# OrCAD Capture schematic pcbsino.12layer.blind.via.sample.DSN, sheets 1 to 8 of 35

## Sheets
1 Pg08: DDR3 Memory 1: size C; title: TITLE; rev: C; company: Texas Instruments; note: Proj PROC053C-003 OPN# TMDSIDK572; note: Catalog Processors BU; note: Final
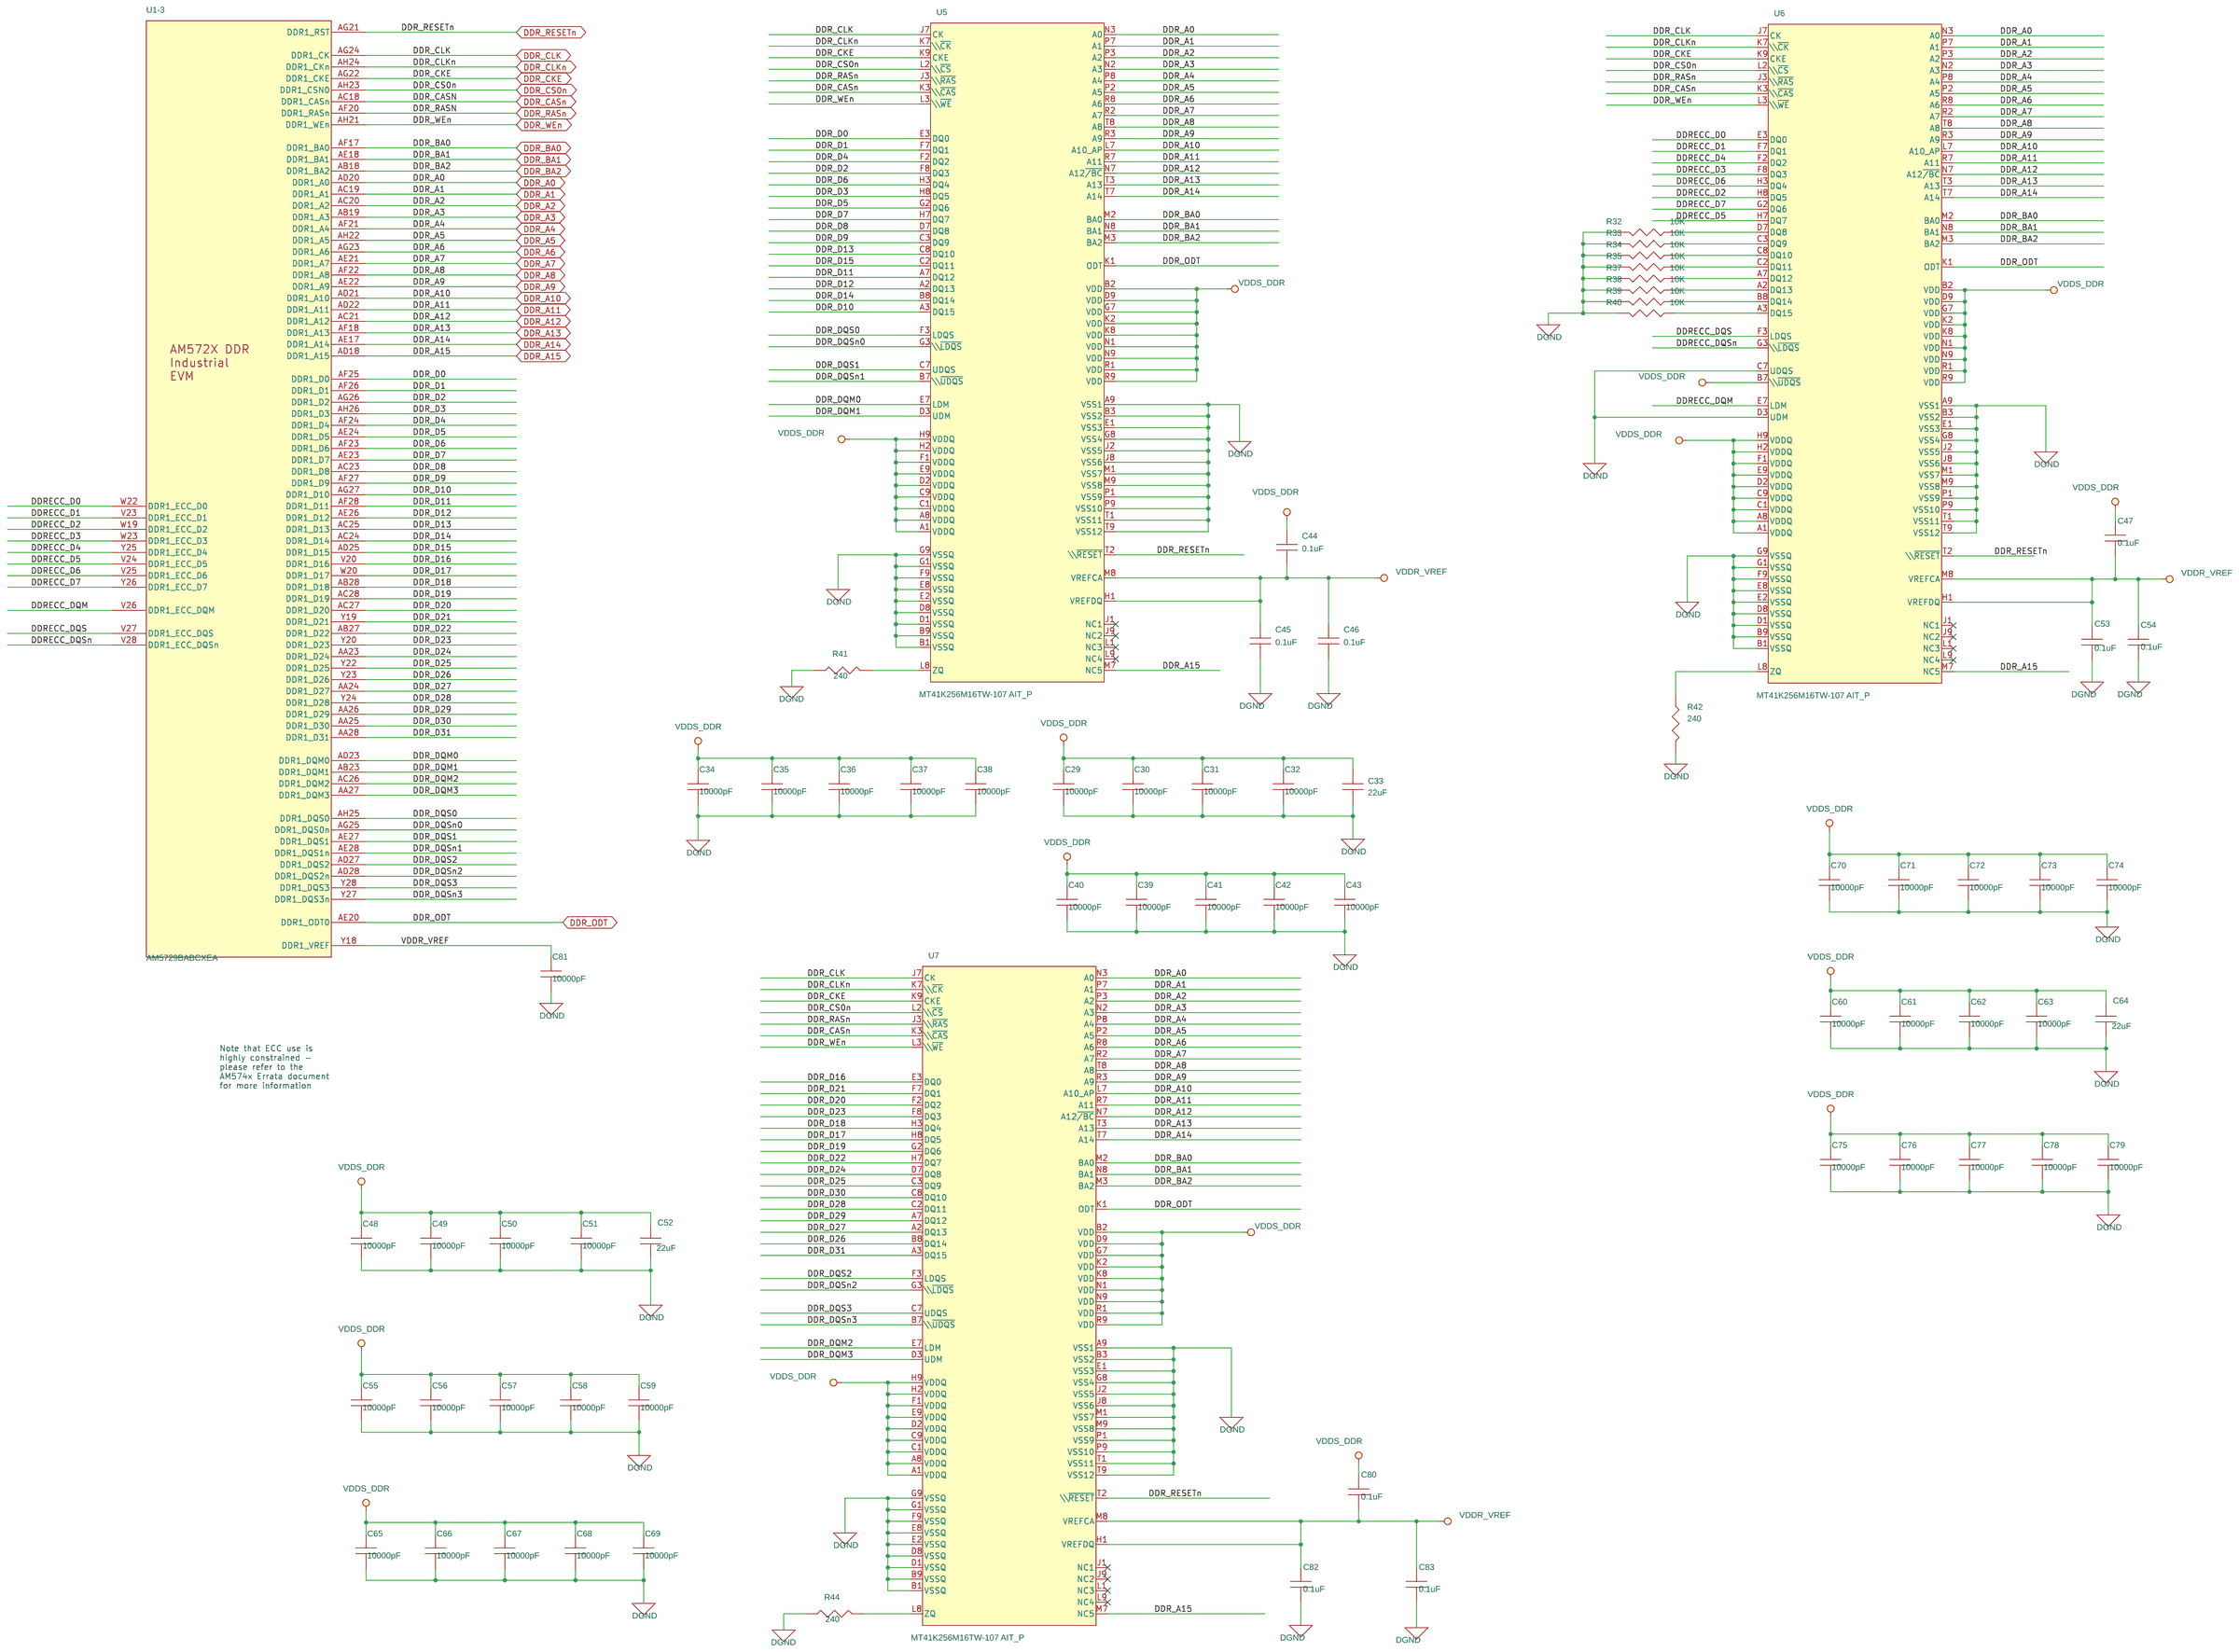
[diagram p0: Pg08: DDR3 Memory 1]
2 Pg24: USB JTAG: size C
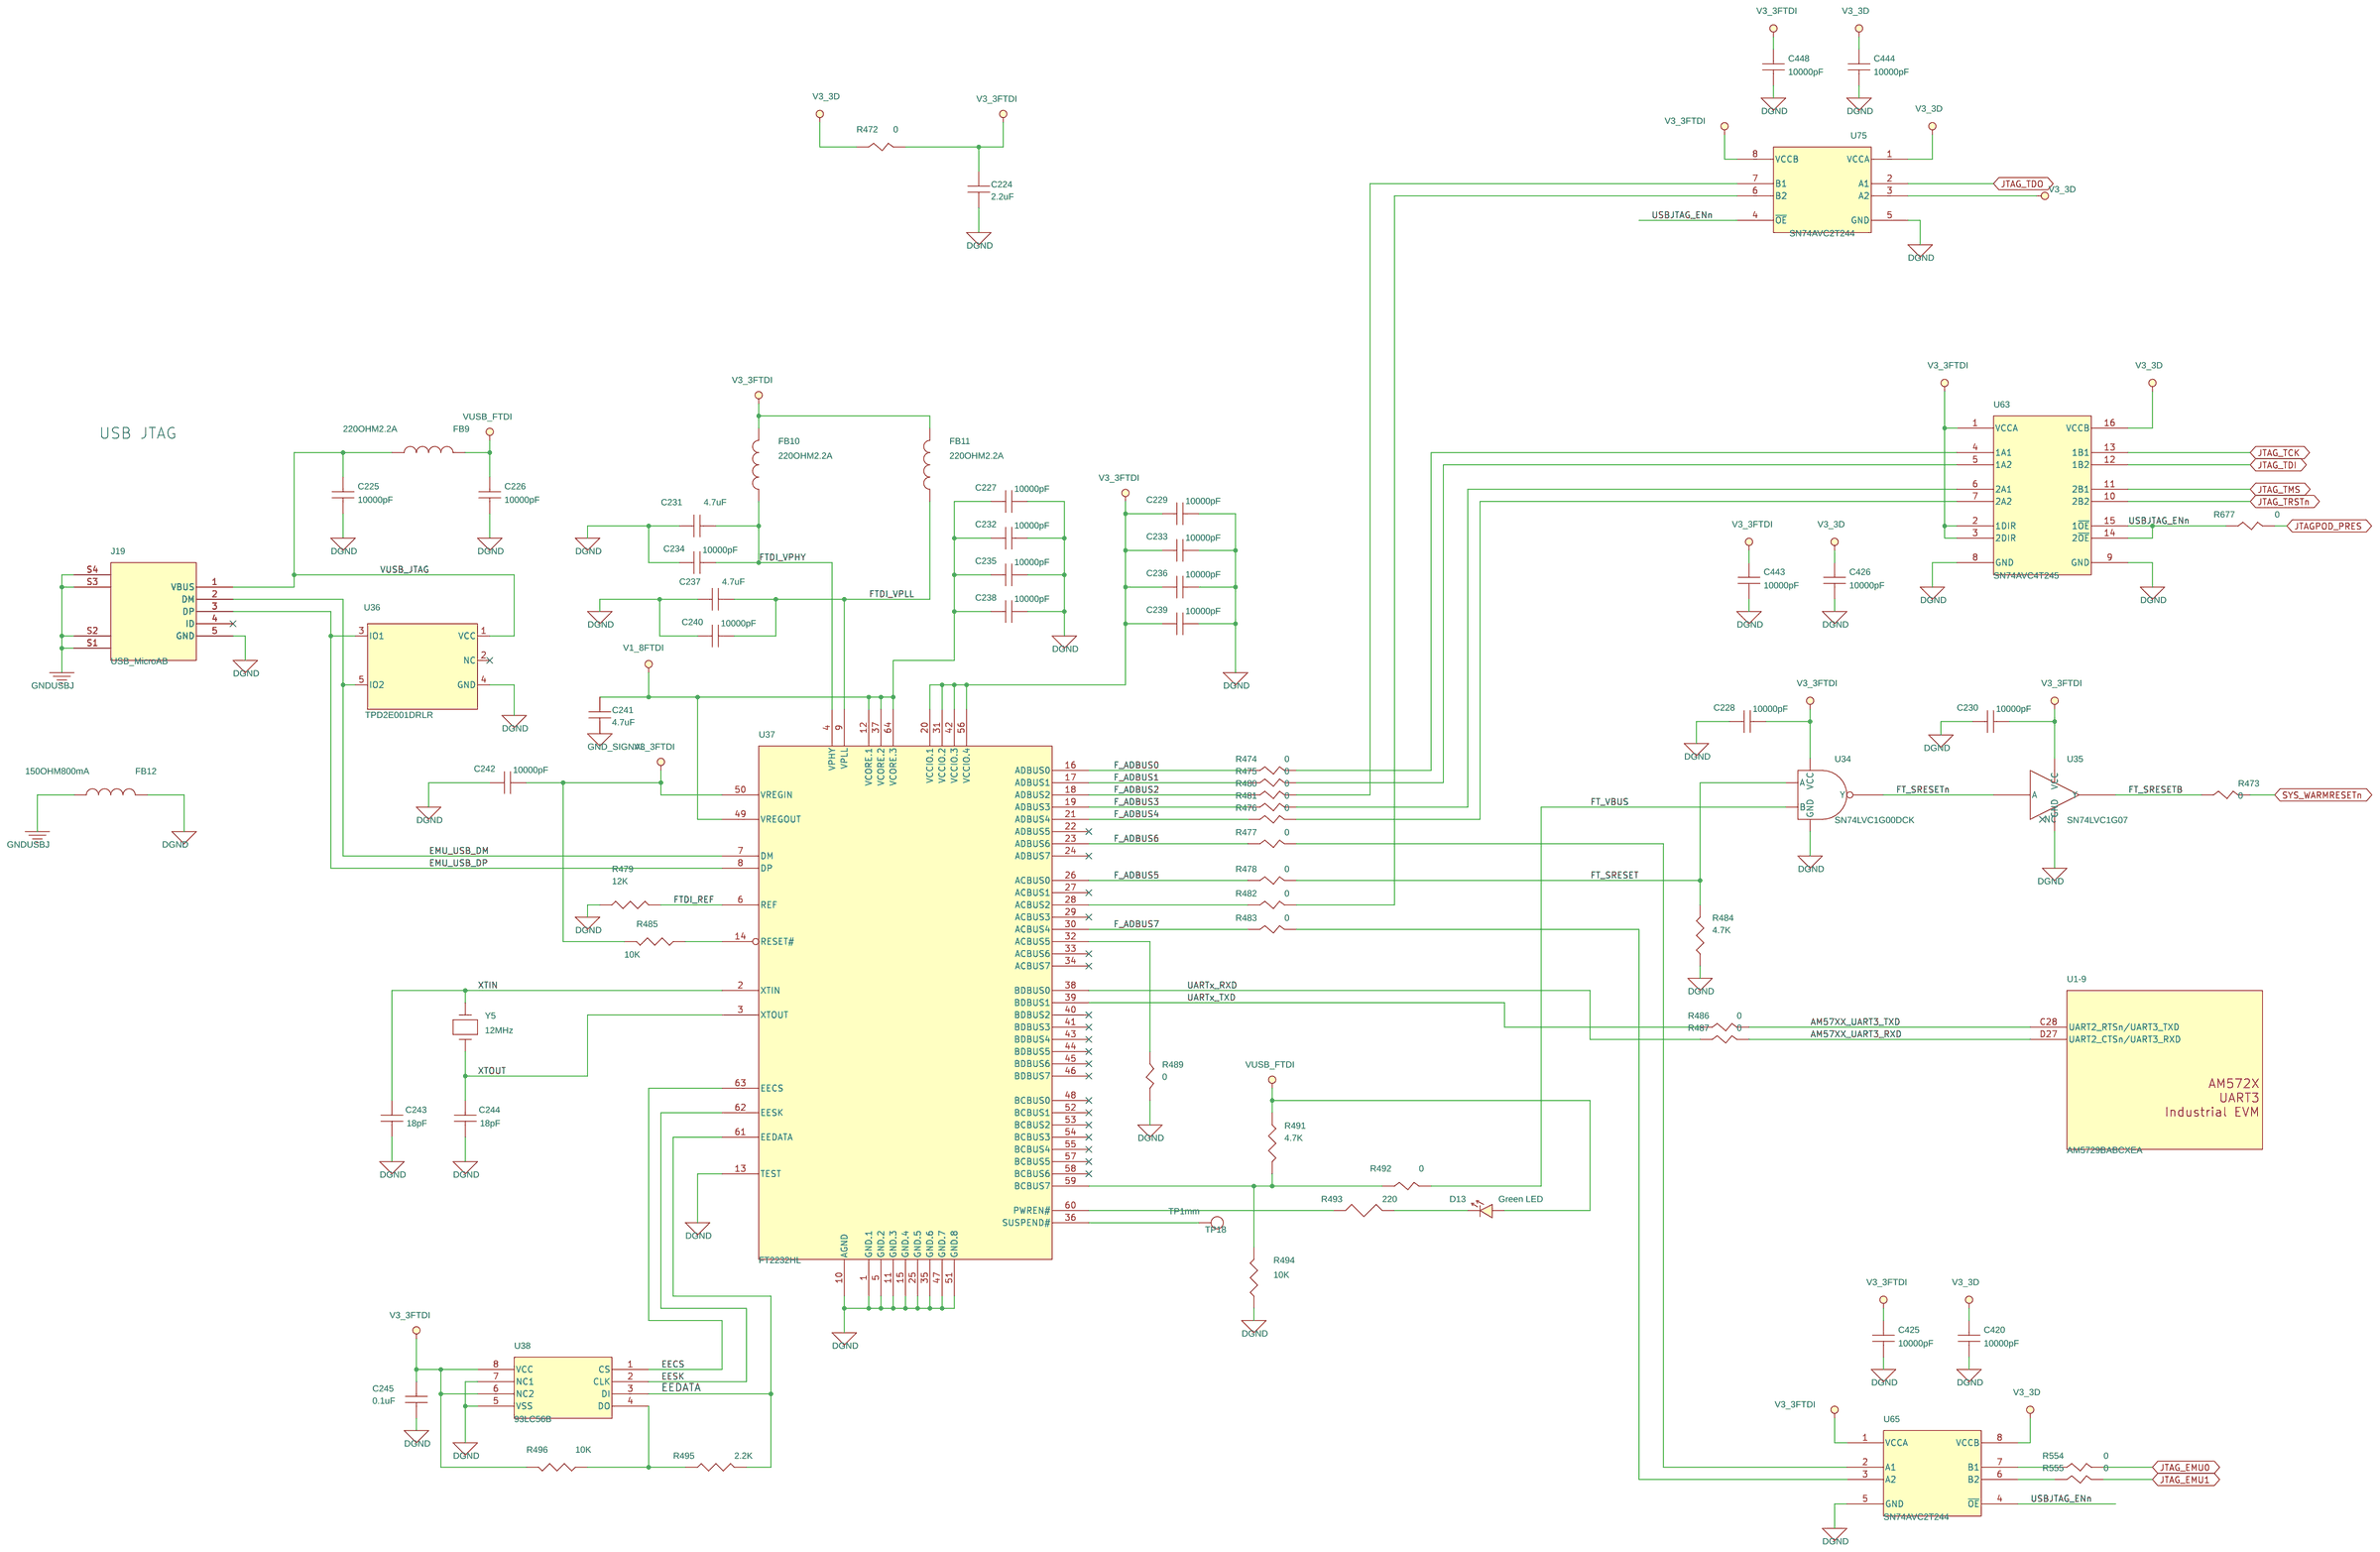
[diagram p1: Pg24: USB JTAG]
3 Pg30: RS-485: size C
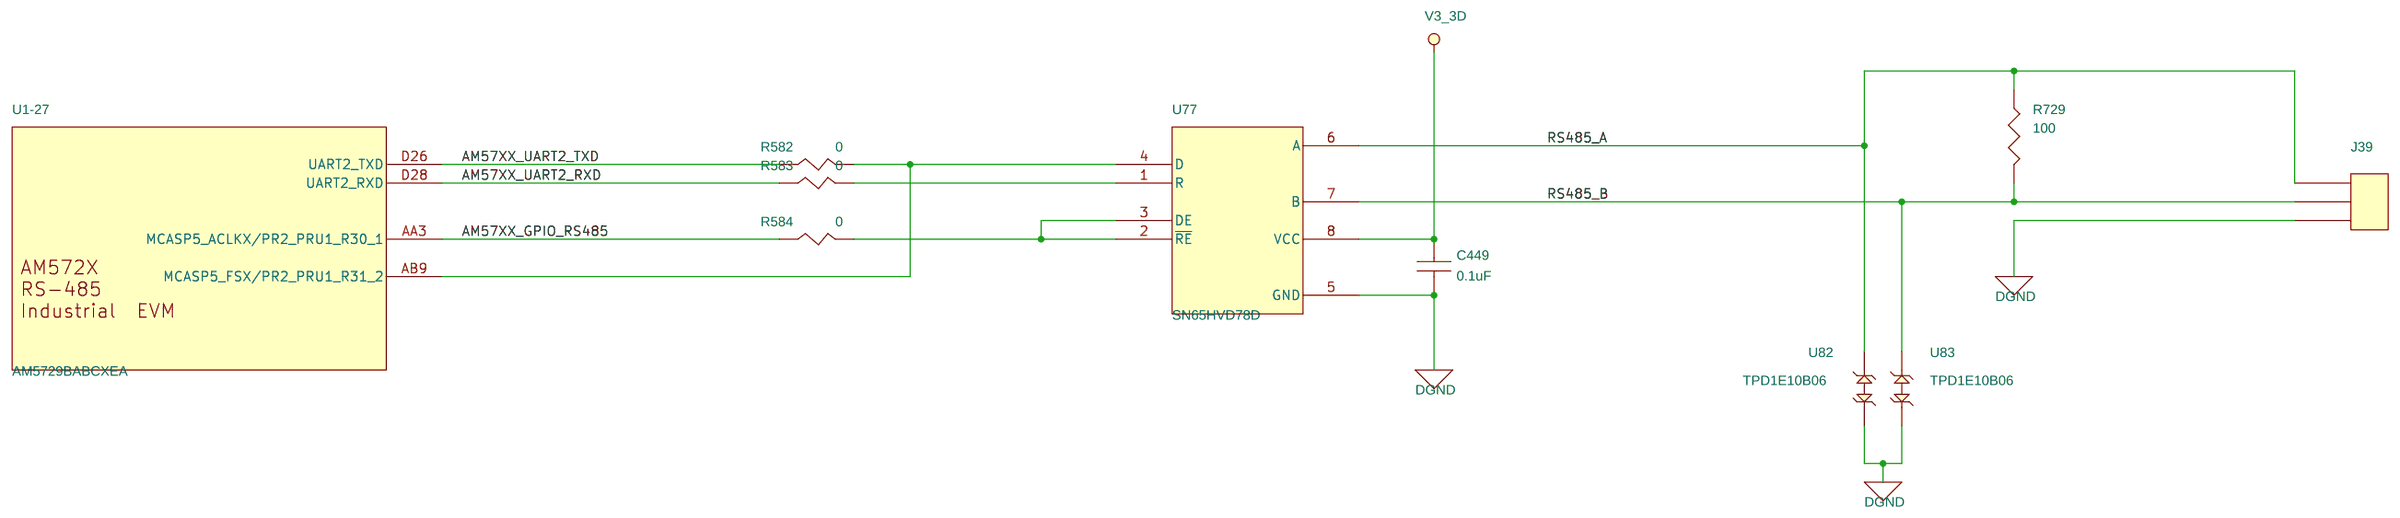
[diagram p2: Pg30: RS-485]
4 Pg22: HDMI: size C
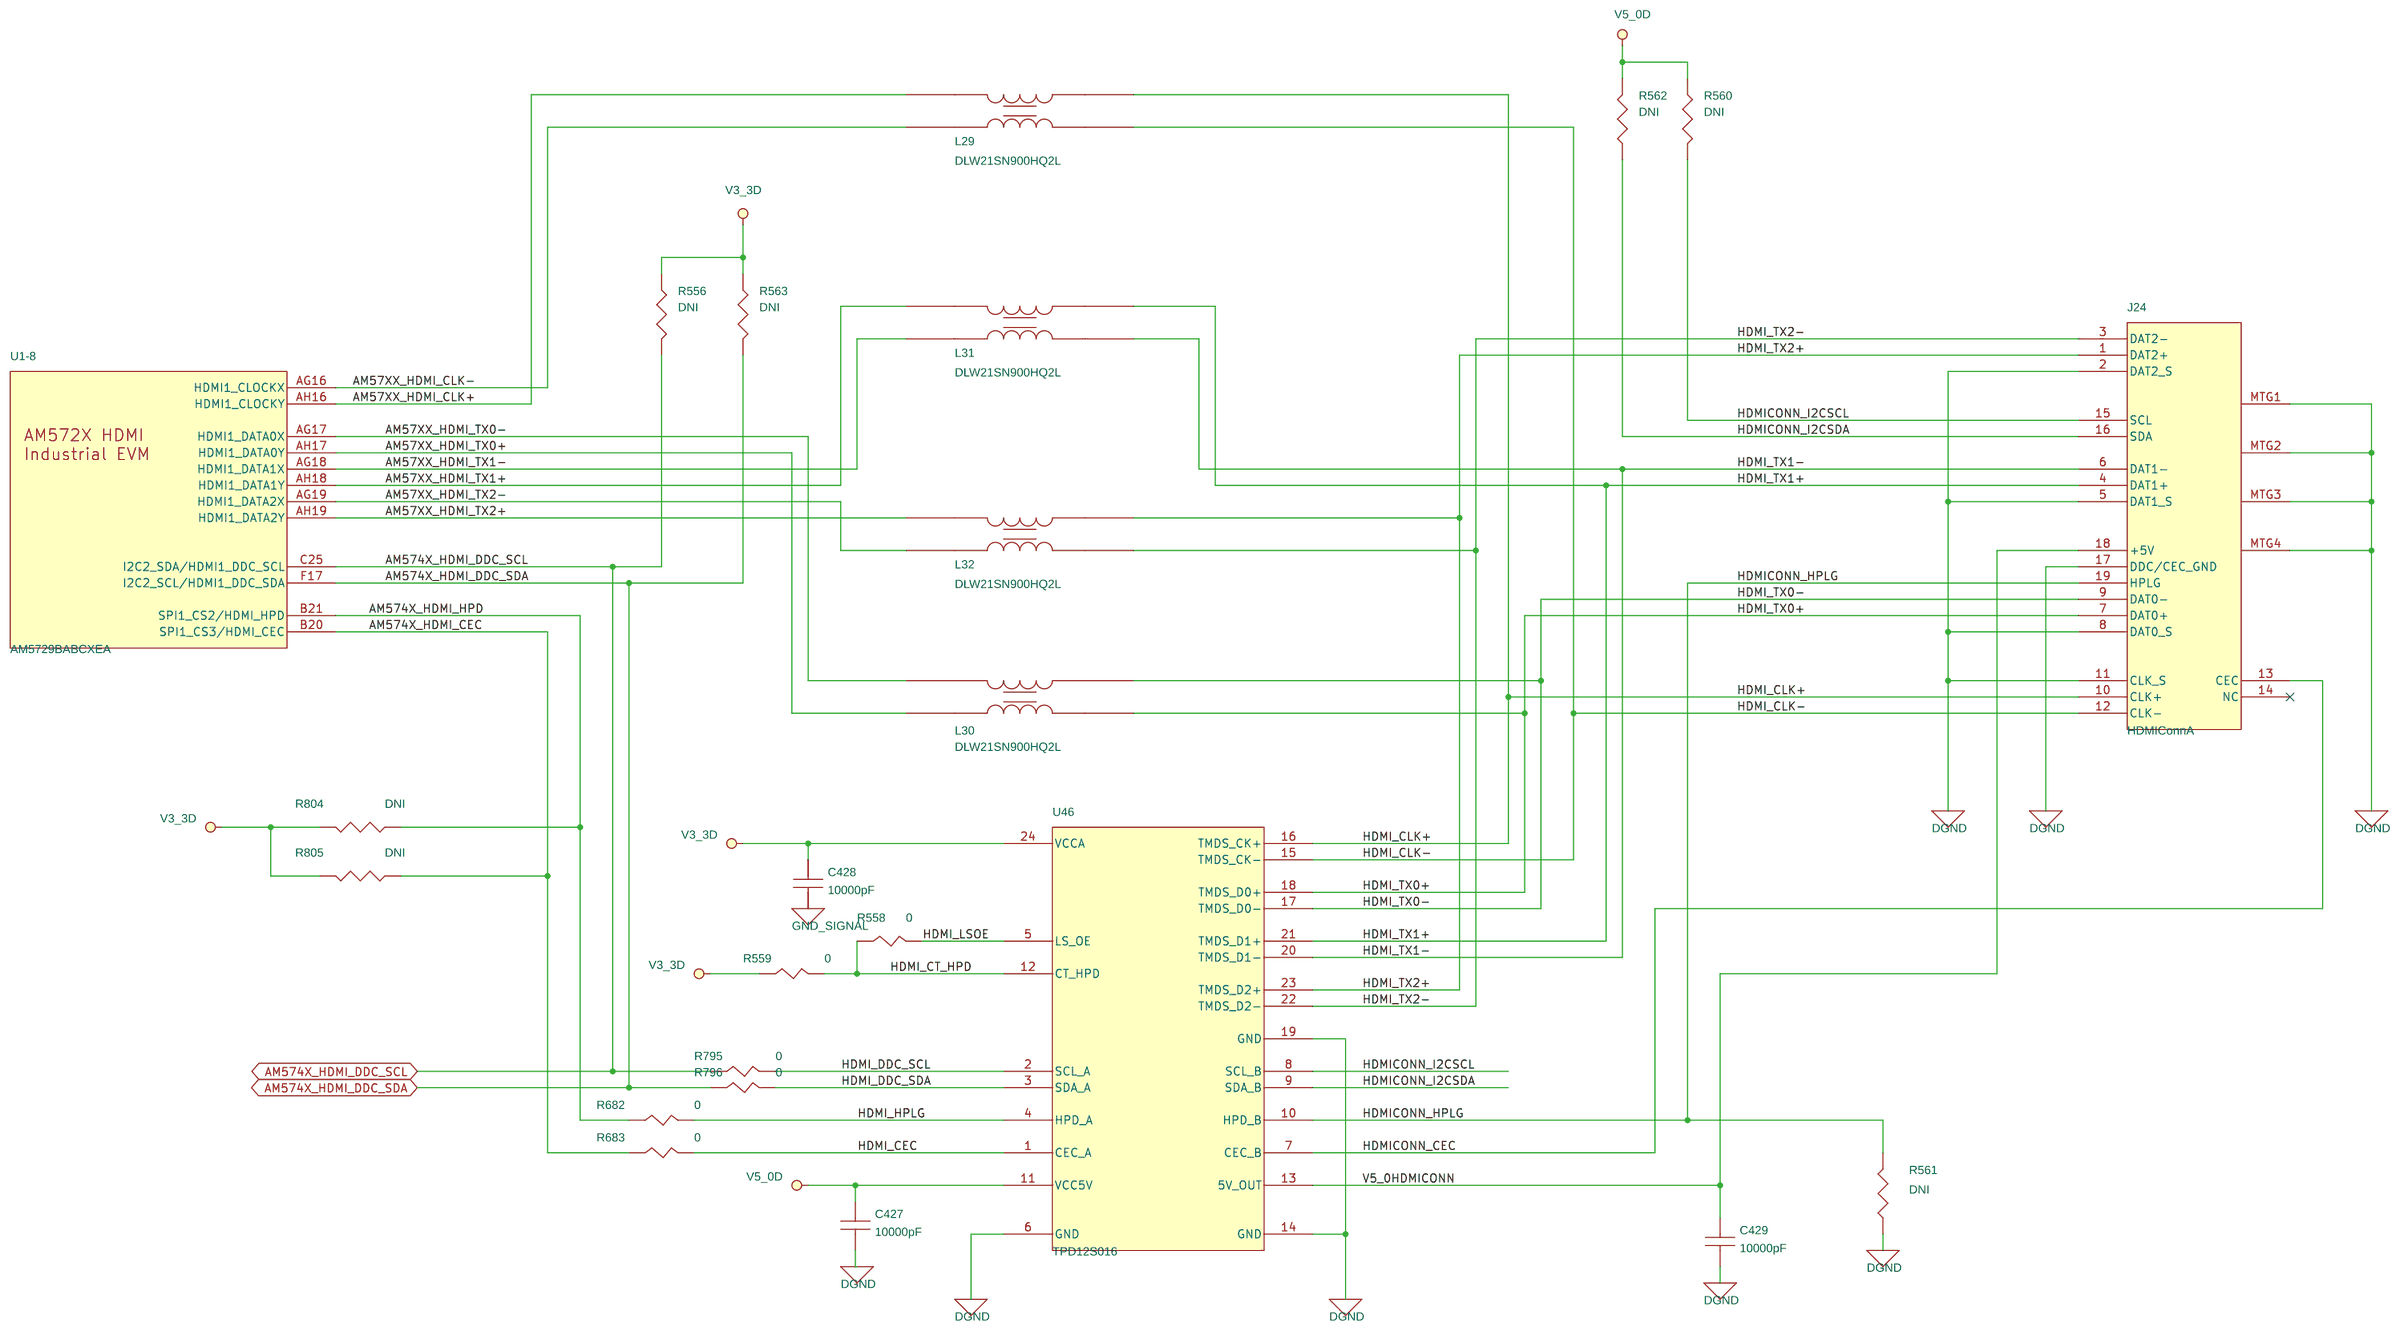
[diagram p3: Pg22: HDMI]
5 Pg21: LCD: size C
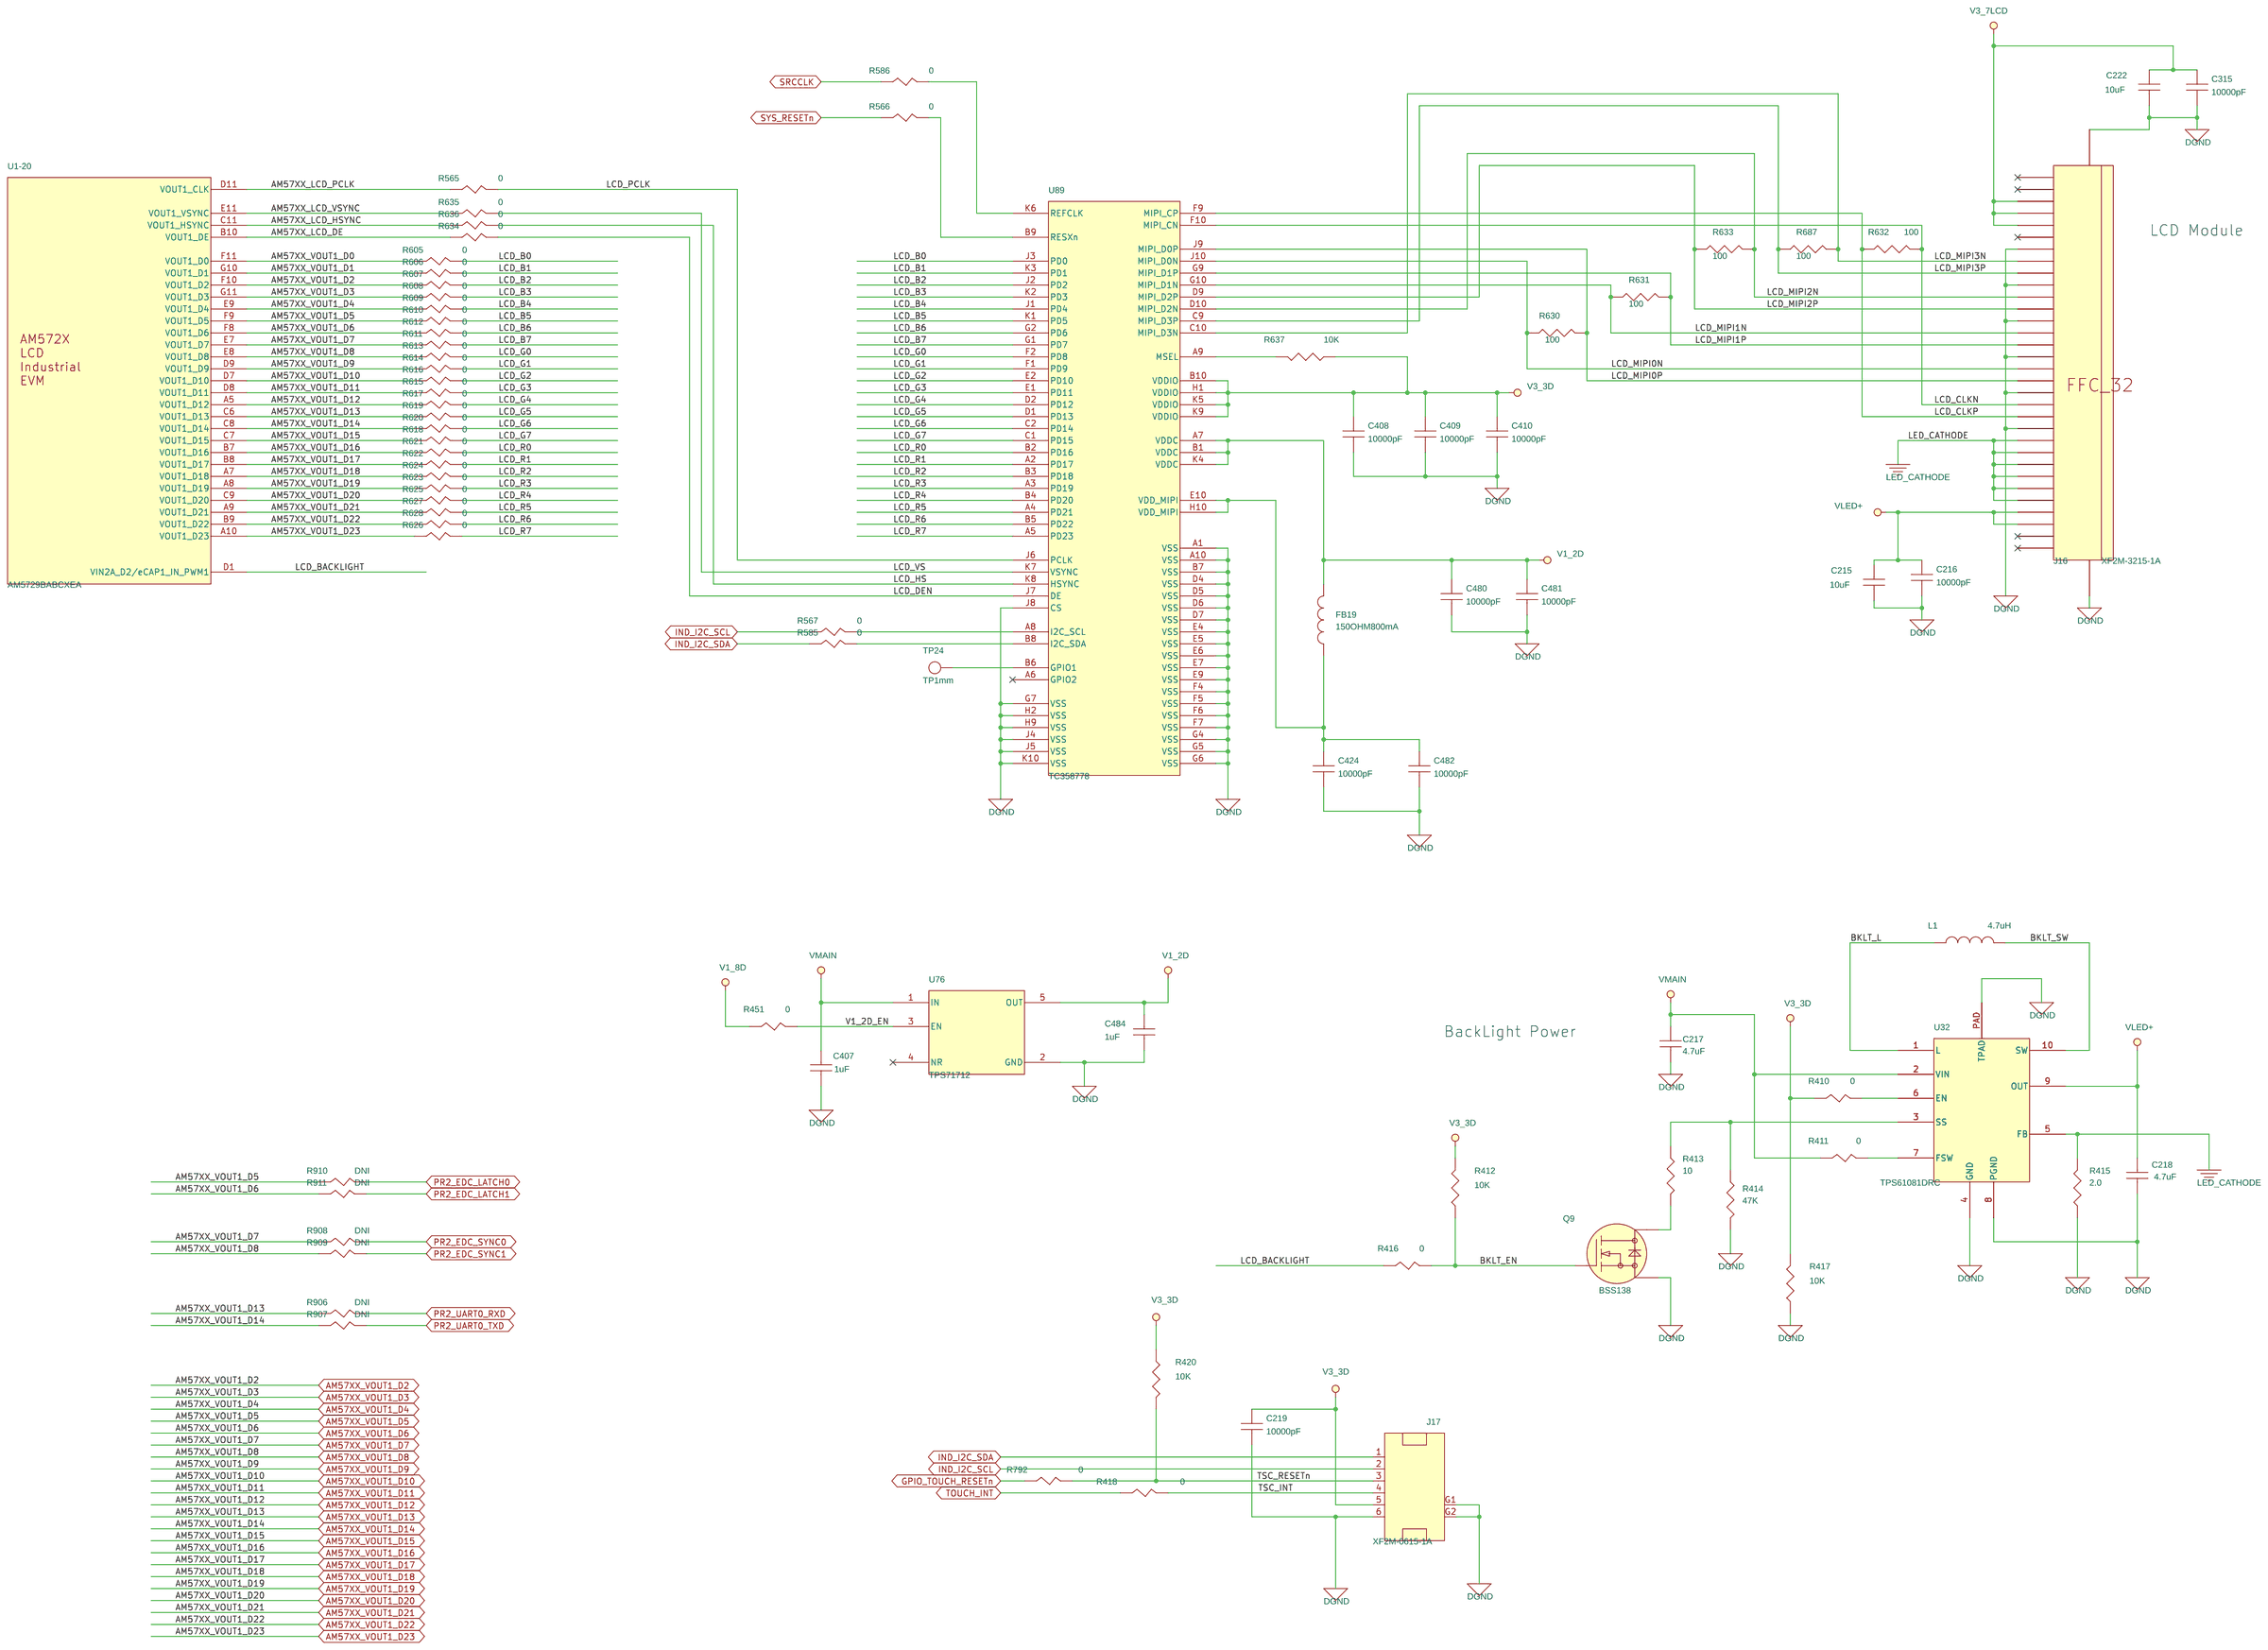
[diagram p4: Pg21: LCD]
6 Pg25: eMMC: size C
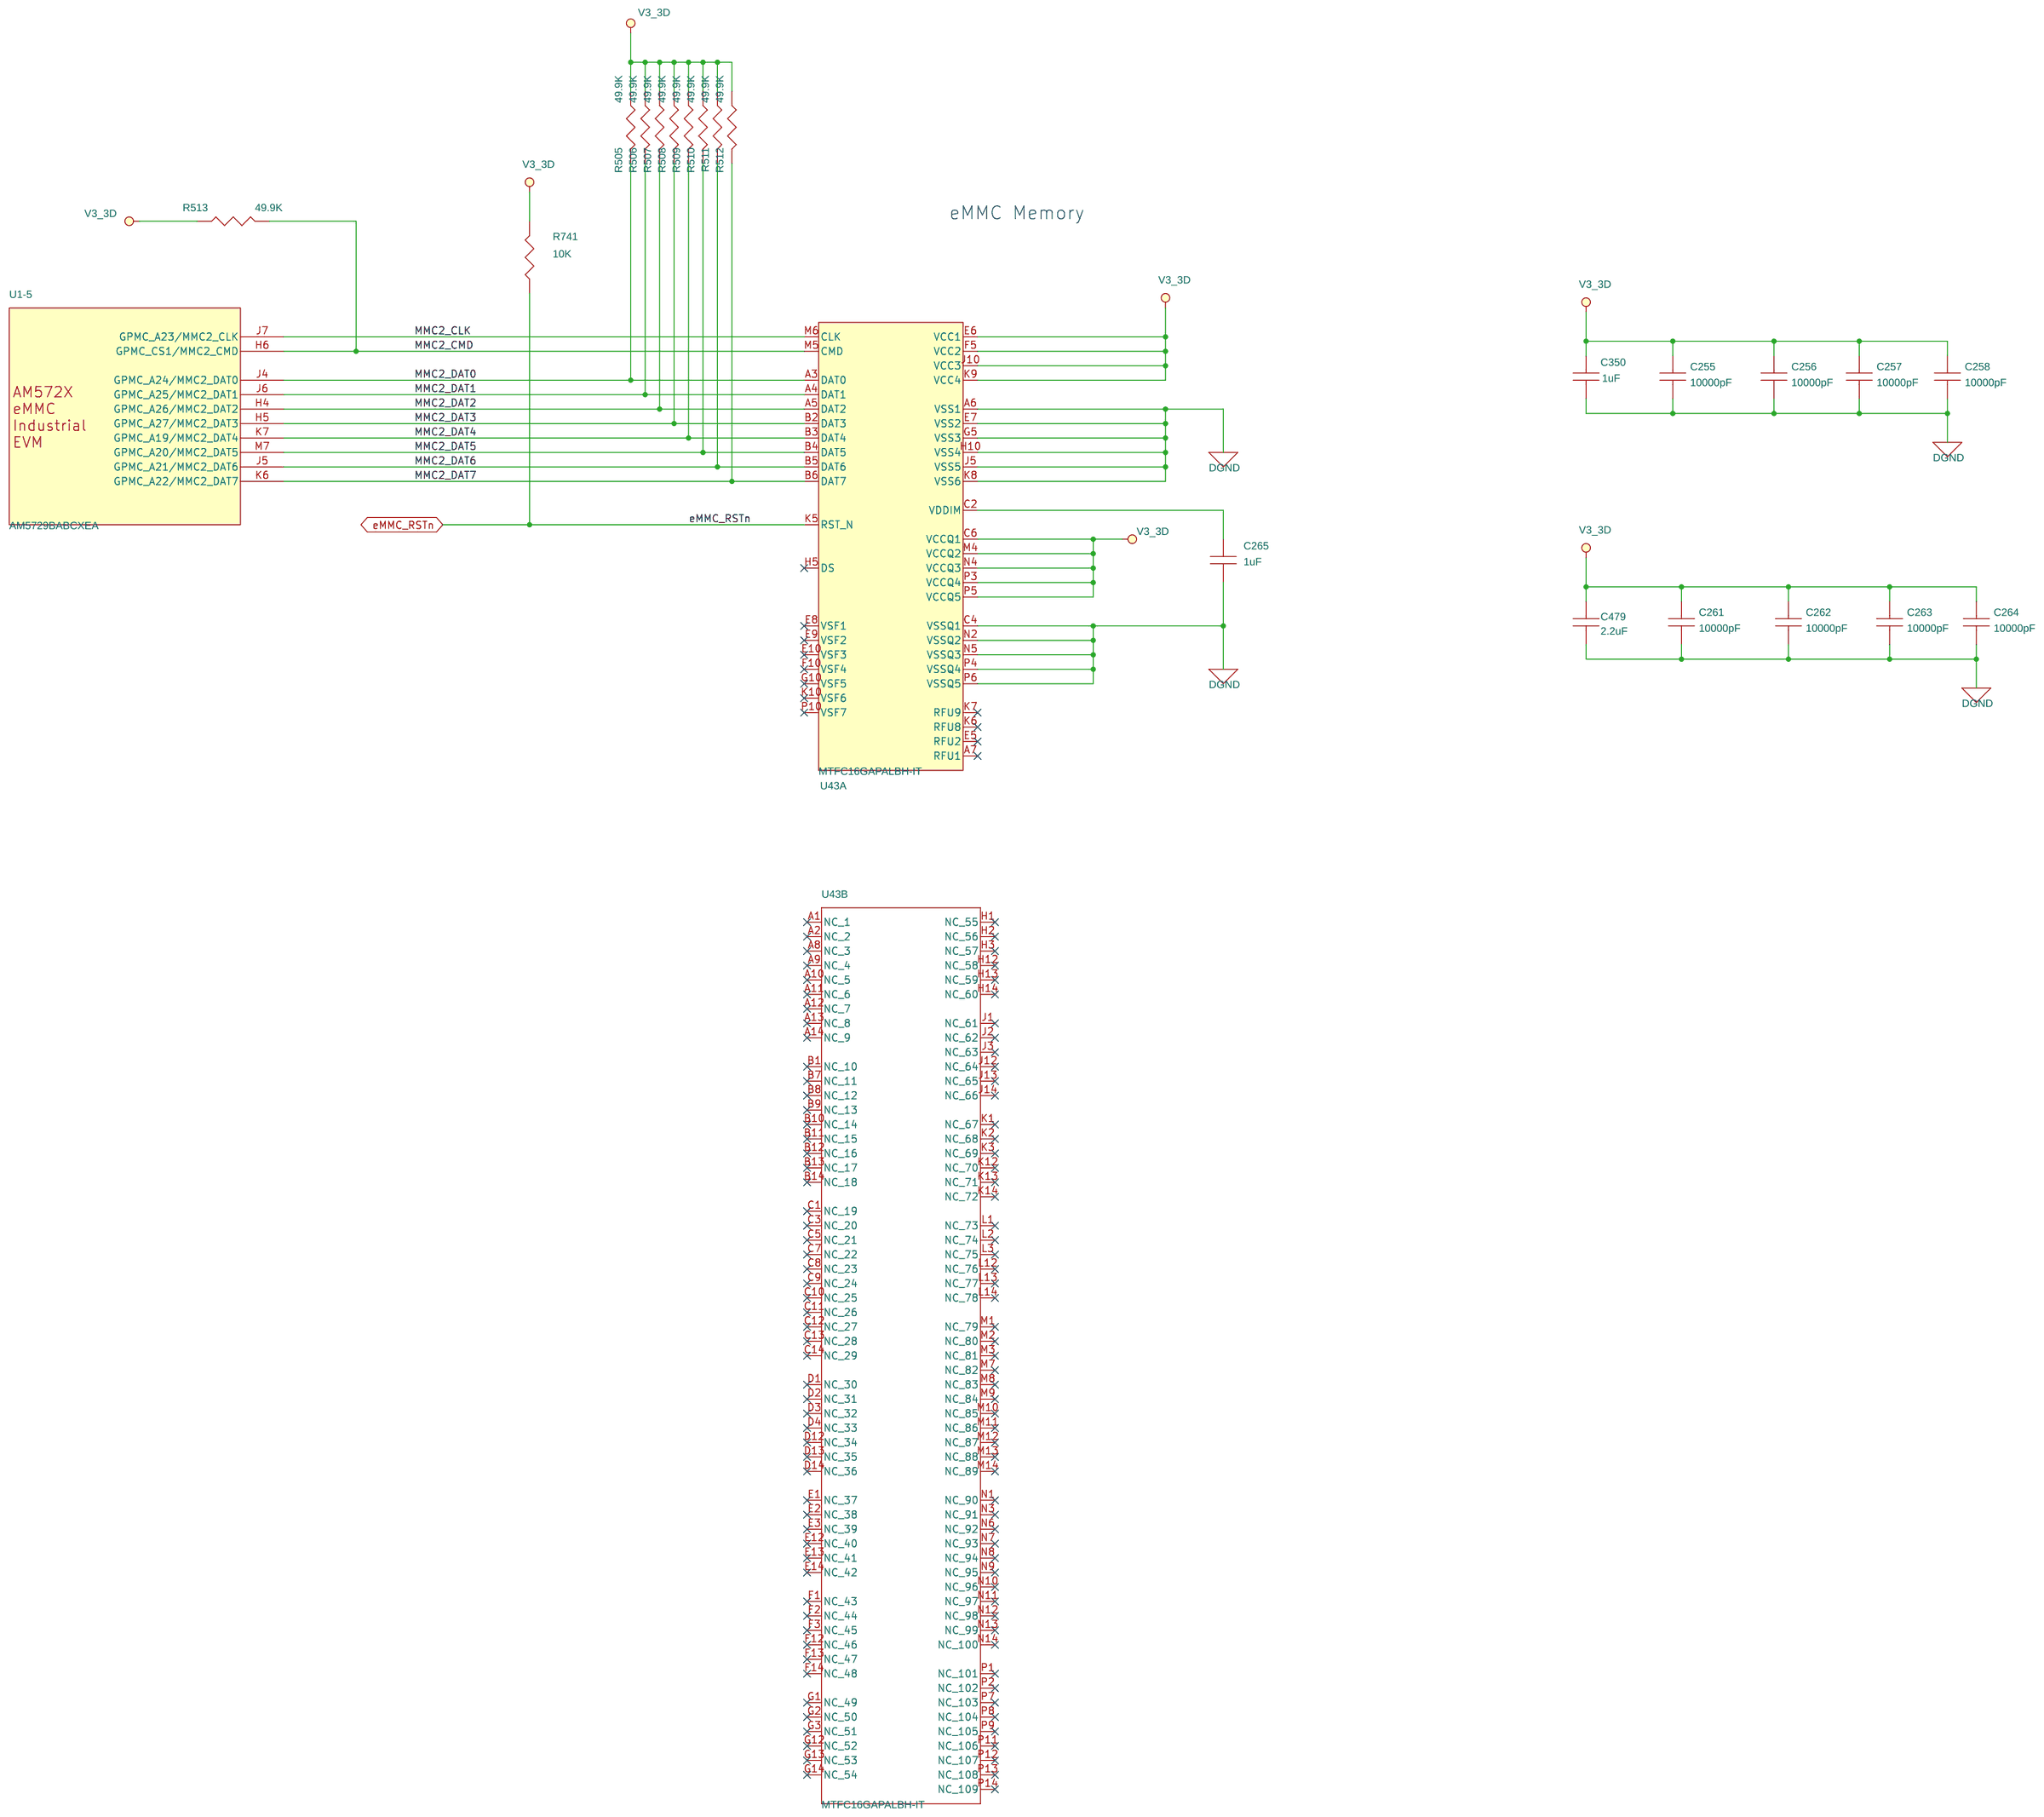
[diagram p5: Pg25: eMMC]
7 Pg35:Hardware
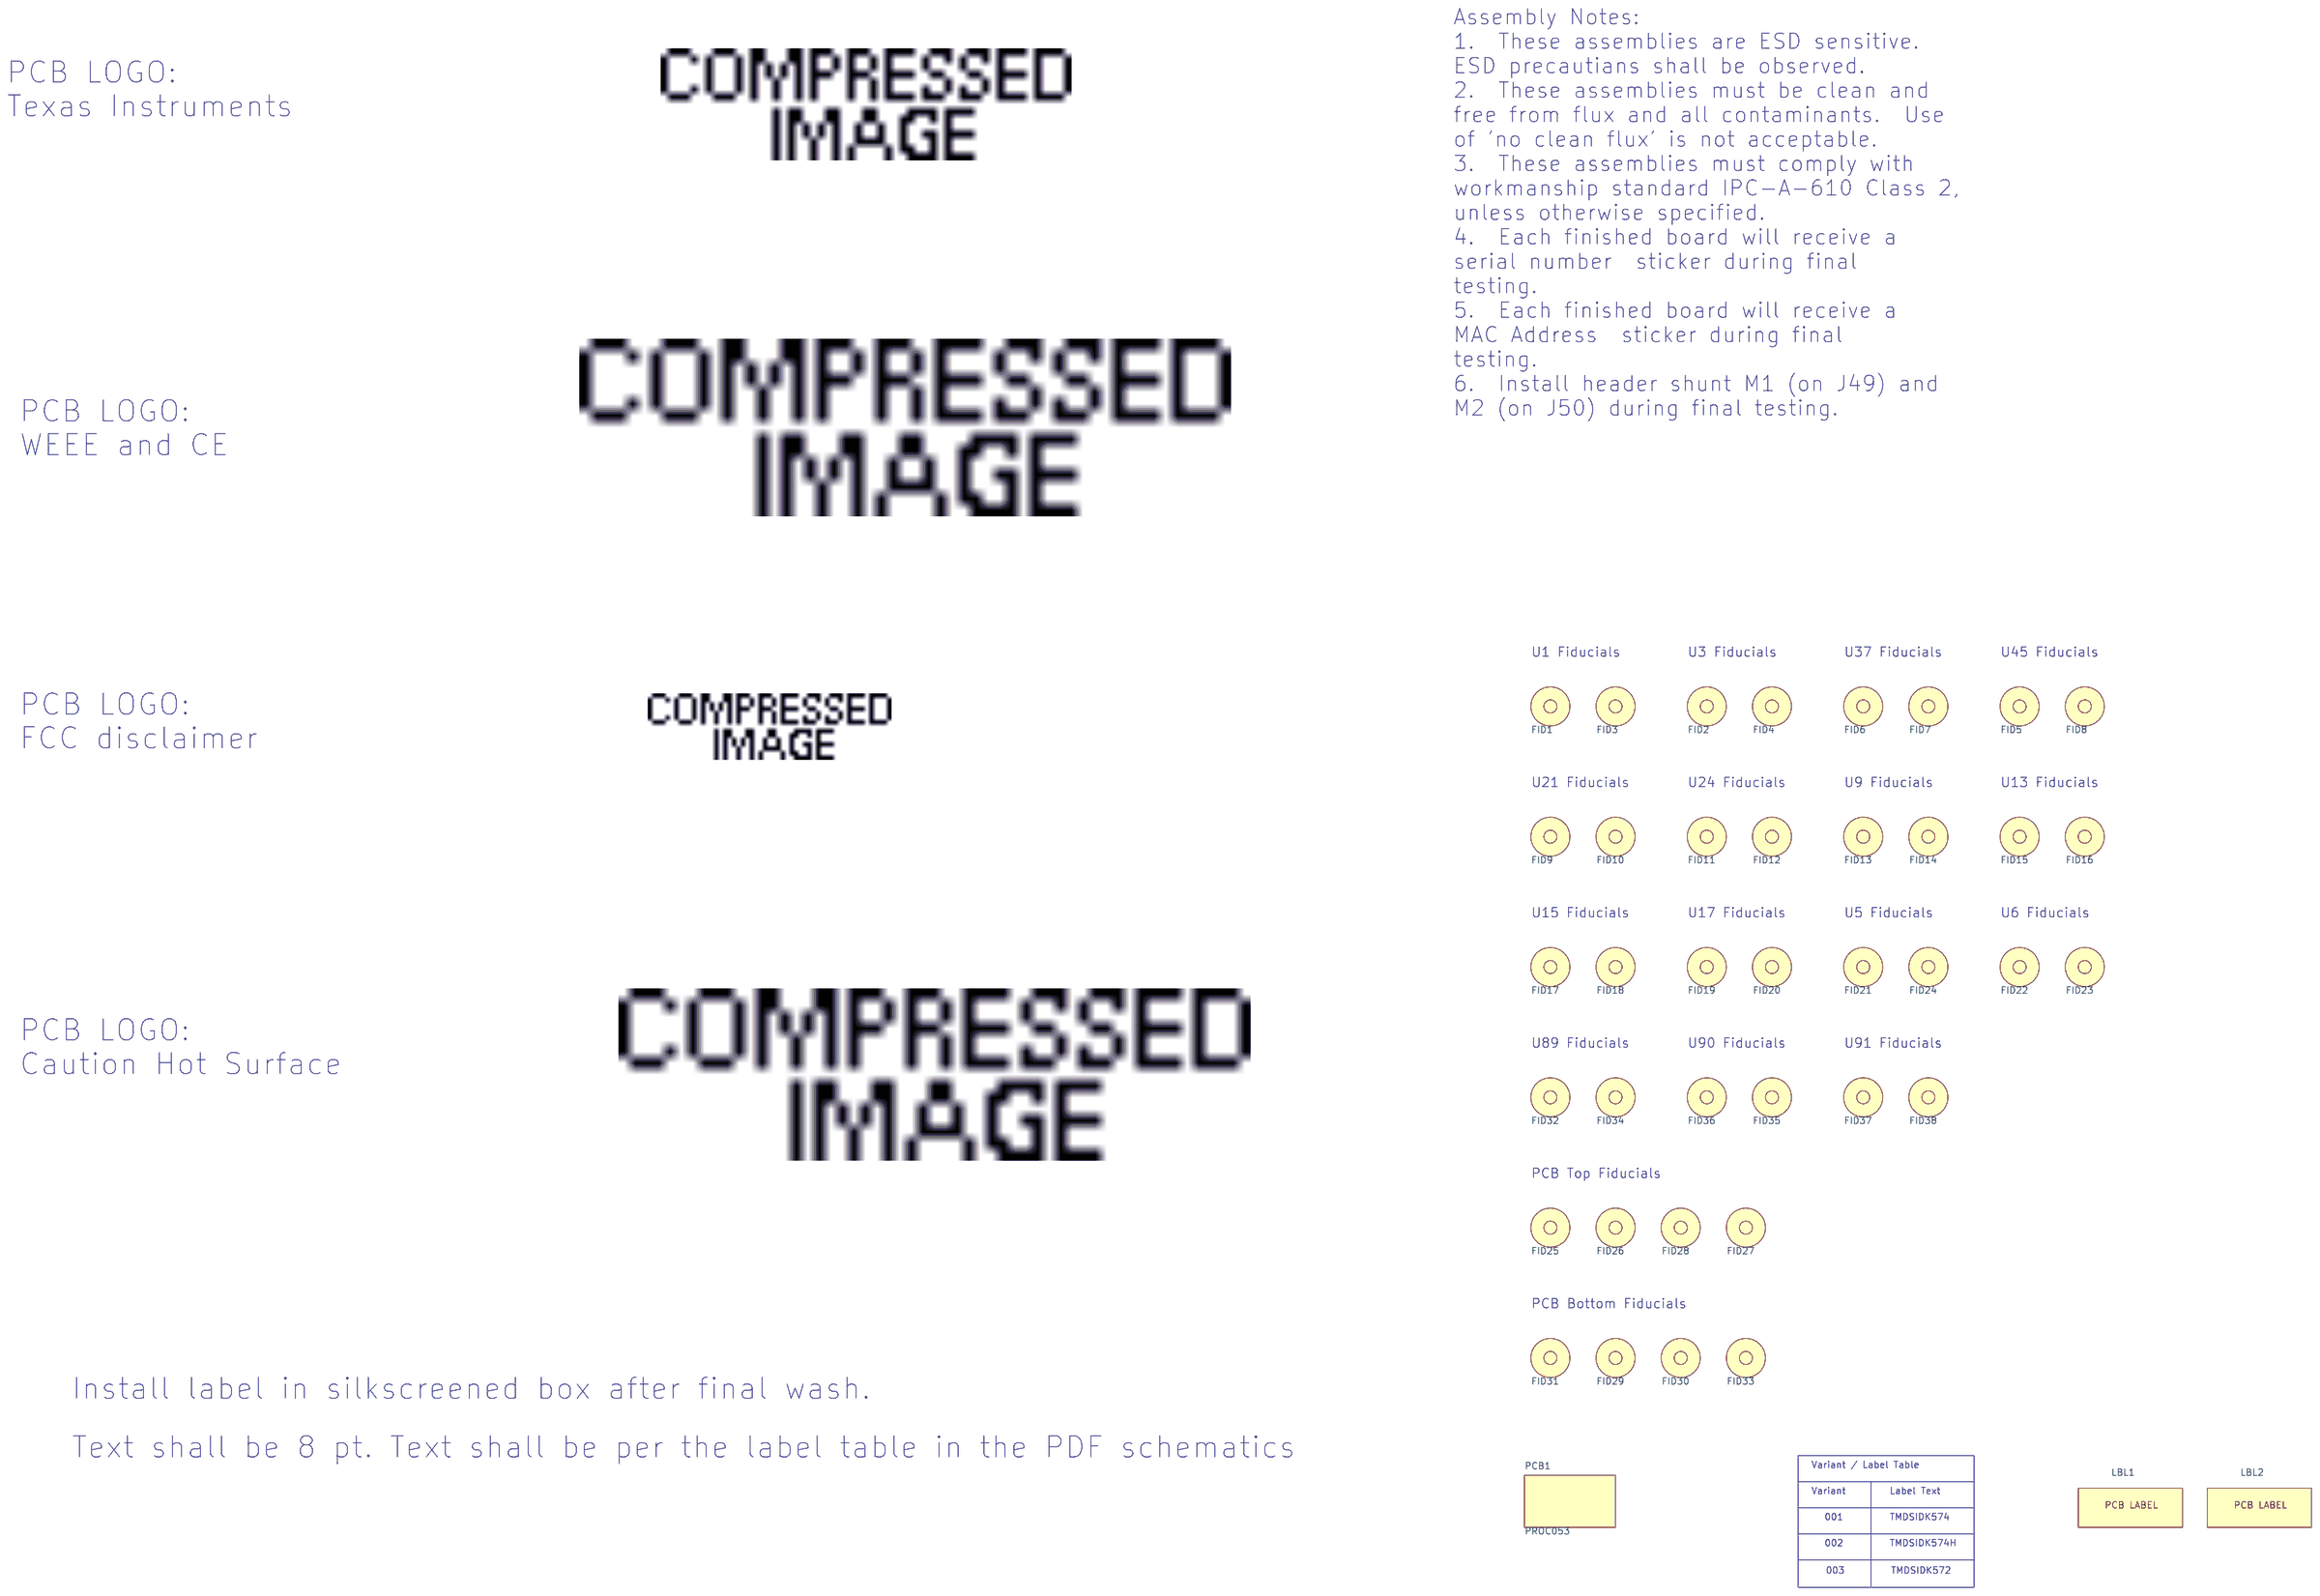
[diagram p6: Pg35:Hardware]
8 Pg28: DCAN #1: size C
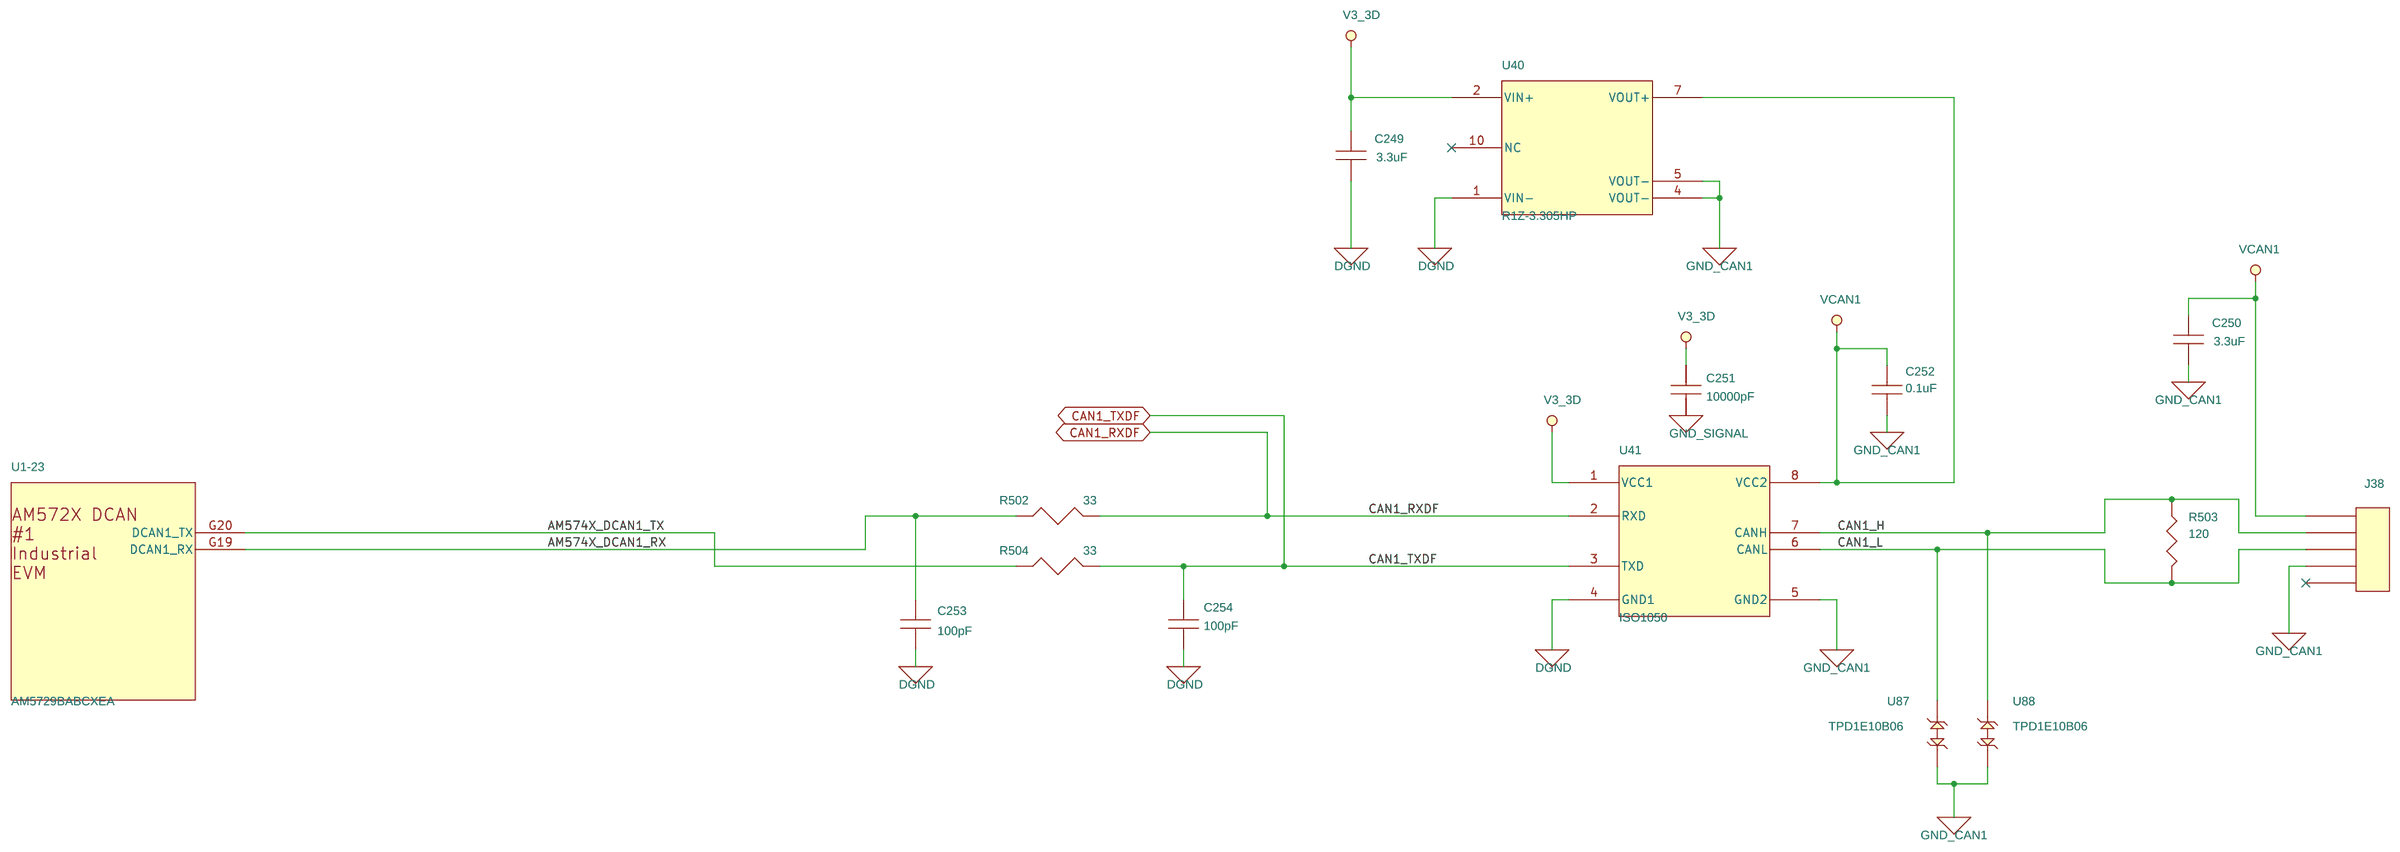
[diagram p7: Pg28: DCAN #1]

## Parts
sheet Pg08: DDR3 Memory 1
C29  10000pF  [CC0402]
C30  10000pF  [CC0402]
C31  10000pF  [CC0402]
C32  10000pF  [CC0402]
C33  22uF  [CC0805]
C34  10000pF  [CC0402]
C35  10000pF  [CC0402]
C36  10000pF  [CC0402]
C37  10000pF  [CC0402]
C38  10000pF  [CC0402]
C39  10000pF  [CC0402]
C40  10000pF  [CC0402]
C41  10000pF  [CC0402]
C42  10000pF  [CC0402]
C43  10000pF  [CC0402]
C44  0.1uF  [CC0402]
C45  0.1uF  [CC0402]
C46  0.1uF  [CC0402]
C47  0.1uF  [CC0402]
C48  10000pF  [CC0402]
C49  10000pF  [CC0402]
C50  10000pF  [CC0402]
C51  10000pF  [CC0402]
C52  22uF  [CC0805]
C53  0.1uF  [CC0402]
C54  0.1uF  [CC0402]
C55  10000pF  [CC0402]
C56  10000pF  [CC0402]
C57  10000pF  [CC0402]
C58  10000pF  [CC0402]
C59  10000pF  [CC0402]
C60  10000pF  [CC0402]
C61  10000pF  [CC0402]
C62  10000pF  [CC0402]
C63  10000pF  [CC0402]
C64  22uF  [CC0805]
C65  10000pF  [CC0402]
C66  10000pF  [CC0402]
C67  10000pF  [CC0402]
C68  10000pF  [CC0402]
C69  10000pF  [CC0402]
C70  10000pF  [CC0402]
C71  10000pF  [CC0402]
C72  10000pF  [CC0402]
C73  10000pF  [CC0402]
C74  10000pF  [CC0402]
C75  10000pF  [CC0402]
C76  10000pF  [CC0402]
C77  10000pF  [CC0402]
C78  10000pF  [CC0402]
C79  10000pF  [CC0402]
C80  0.1uF  [CC0402]
C81  10000pF  [CC0402]
C82  0.1uF  [CC0402]
C83  0.1uF  [CC0402]
R32  10K  [SM-7351-RES-0402]
R33  10K  [SM-7351-RES-0402]
R34  10K  [SM-7351-RES-0402]
R35  10K  [SM-7351-RES-0402]
R37  10K  [SM-7351-RES-0402]
R38  10K  [SM-7351-RES-0402]
R39  10K  [SM-7351-RES-0402]
R40  10K  [SM-7351-RES-0402]
R41  240  [sm-7351-res-0402]
R42  240  [sm-7351-res-0402]
R44  240  [sm-7351-res-0402]
U5  MT41K256M16TW-107 AIT_P  [BGA96C80P9X16_800X1400X120]
U6  MT41K256M16TW-107 AIT_P  [BGA96C80P9X16_800X1400X120]
U7  MT41K256M16TW-107 AIT_P  [BGA96C80P9X16_800X1400X120]
sheet Pg21: LCD
C215  10uF  [CC0805]
C216  10000pF  [CC0402]
C217  4.7uF  [SM-7351-CAP-0603]
C218  4.7uF  [CC0805]
C219  10000pF  [CC0402]
C222  10uF  [CC0805]
C315  10000pF  [CC0402]
C407  1uF  [CC0402]
C408  10000pF  [CC0402]
C409  10000pF  [CC0402]
C410  10000pF  [CC0402]
C424  10000pF  [CC0402]
C480  10000pF  [CC0402]
C481  10000pF  [CC0402]
C482  10000pF  [CC0402]
C484  1uF  [CC0402]
FB19  150OHM800mA  [sm-7351-ind-0805]
J16  XF2M-3215-1A  [CNXF2M-3215-1A]
J17  XF2M-0615-1A  [OMRON_XF2M-0615-1A]
L1  4.7uH  [vlcf5020t]
Q9  BSS138  [SOT23-3]
R410  0  [SM-7351-RES-0402]
R411  0  [SM-7351-RES-0402]
R412  10K  [SM-7351-RES-0402]
R413  10  [SM-7351-RES-0402]
R414  47K  [SM-7351-RES-0402]
R415  2.0  [SM-7351-RES-0603]
R416  0  [SM-7351-RES-0402]
R417  10K  [SM-7351-RES-0402]
R418  0  [SM-7351-RES-0402]
R420  10K  [SM-7351-RES-0402]
R451  0  [SM-7351-RES-0402]
R565  0  [SM-7351-RES-0402]
R566  0  [SM-7351-RES-0402]
R567  0  [SM-7351-RES-0402]
R585  0  [SM-7351-RES-0402]
R586  0  [SM-7351-RES-0402]
R605  0  [SM-7351-RES-0402]
R606  0  [SM-7351-RES-0402]
R607  0  [SM-7351-RES-0402]
R608  0  [SM-7351-RES-0402]
R609  0  [SM-7351-RES-0402]
R610  0  [SM-7351-RES-0402]
R611  0  [SM-7351-RES-0402]
R612  0  [SM-7351-RES-0402]
R613  0  [SM-7351-RES-0402]
R614  0  [SM-7351-RES-0402]
R615  0  [SM-7351-RES-0402]
R616  0  [SM-7351-RES-0402]
R617  0  [SM-7351-RES-0402]
R618  0  [SM-7351-RES-0402]
R619  0  [SM-7351-RES-0402]
R620  0  [SM-7351-RES-0402]
R621  0  [SM-7351-RES-0402]
R622  0  [SM-7351-RES-0402]
R623  0  [SM-7351-RES-0402]
R624  0  [SM-7351-RES-0402]
R625  0  [SM-7351-RES-0402]
R626  0  [SM-7351-RES-0402]
R627  0  [SM-7351-RES-0402]
R628  0  [SM-7351-RES-0402]
R630  100  [SM-7351-RES-0402]
R631  100  [SM-7351-RES-0402]
R632  100  [SM-7351-RES-0402]
R633  100  [SM-7351-RES-0402]
R634  0  [SM-7351-RES-0402]
R635  0  [SM-7351-RES-0402]
R636  0  [SM-7351-RES-0402]
R637  10K  [SM-7351-RES-0402]
R687  100  [SM-7351-RES-0402]
R792  0  [SM-7351-RES-0402]
R906  DNI  [SM-7351-RES-0402]
R907  DNI  [SM-7351-RES-0402]
R908  DNI  [SM-7351-RES-0402]
R909  DNI  [SM-7351-RES-0402]
R910  DNI  [SM-7351-RES-0402]
R911  DNI  [SM-7351-RES-0402]
TP24  TP1mm  [tp_smd1mmcircle]
U32  TPS61081DRC  [u_10_drc]
U76  TPS71712  [smdsc70-5]
U89  TC358778  [BGA7X7-80-39M]
sheet Pg22: HDMI
C427  10000pF  [CC0402]
C428  10000pF  [CC0402]
C429  10000pF  [CC0402]
J24  HDMIConnA  [smd_hdmia_ra]
L29  DLW21SN900HQ2L  [filt-dlw21s]
L30  DLW21SN900HQ2L  [filt-dlw21s]
L31  DLW21SN900HQ2L  [filt-dlw21s]
L32  DLW21SN900HQ2L  [filt-dlw21s]
R556  DNI  [sm-7351-res-0402]
R558  0  [SM-7351-RES-0402]
R559  0  [SM-7351-RES-0402]
R560  DNI  [SM-7351-RES-0402]
R561  DNI  [SM-7351-RES-0402]
R562  DNI  [SM-7351-RES-0402]
R563  DNI  [sm-7351-res-0402]
R682  0  [SM-7351-RES-0402]
R683  0  [SM-7351-RES-0402]
R795  0  [SM-7351-RES-0402]
R796  0  [SM-7351-RES-0402]
R804  DNI  [SM-7351-RES-0402]
R805  DNI  [SM-7351-RES-0402]
U1  AM5729BABCXEA  [BGA23X23-760-117M]  (sections -1,-10,-11,-12,-13,-14,-15,-16,-17,-18,-19,-2,-20,-21,-22,-23,-24,-25,-26,-27,-28,-29,-3,-4,-5,-6,-7,-8,-9)
U46  TPD12S016  [pw_24pin_tssop]
sheet Pg24: USB JTAG
C224  2.2uF  [SM-7351-CAP-0805]
C225  10000pF  [CC0402]
C226  10000pF  [CC0402]
C227  10000pF  [CC0402]
C228  10000pF  [CC0402]
C229  10000pF  [CC0402]
C230  10000pF  [CC0402]
C231  4.7uF  [SM-7351-CAP-0603]
C232  10000pF  [CC0402]
C233  10000pF  [CC0402]
C234  10000pF  [CC0402]
C235  10000pF  [CC0402]
C236  10000pF  [CC0402]
C237  4.7uF  [SM-7351-CAP-0603]
C238  10000pF  [CC0402]
C239  10000pF  [CC0402]
C240  10000pF  [CC0402]
C241  4.7uF  [SM-7351-CAP-0603]
C242  10000pF  [CC0402]
C243  18pF  [CC0402]
C244  18pF  [CC0402]
C245  0.1uF  [CC0402]
C420  10000pF  [CC0402]
C425  10000pF  [CC0402]
C426  10000pF  [CC0402]
C443  10000pF  [CC0402]
C444  10000pF  [CC0402]
C448  10000pF  [CC0402]
D13  Green LED  [sm_led_0805]
FB9  220OHM2.2A  [sm-7351-ind-0603]
FB10  220OHM2.2A  [sm-7351-ind-0603]
FB11  220OHM2.2A  [sm-7351-ind-0603]
FB12  150OHM800mA  [sm-7351-ind-0805]
J19  USB_MicroAB  [ZX62-AB-5PA]
R472  0  [SM-7351-RES-0603]
R473  0  [SM-7351-RES-0402]
R474  0  [SM-7351-RES-0402]
R475  0  [SM-7351-RES-0402]
R476  0  [SM-7351-RES-0402]
R477  0  [SM-7351-RES-0402]
R478  0  [SM-7351-RES-0402]
R479  12K  [SM-7351-RES-0402]
R480  0  [SM-7351-RES-0402]
R481  0  [SM-7351-RES-0402]
R482  0  [SM-7351-RES-0402]
R483  0  [SM-7351-RES-0402]
R484  4.7K  [SM-7351-RES-0402]
R485  10K  [SM-7351-RES-0402]
R486  0  [SM-7351-RES-0402]
R487  0  [SM-7351-RES-0402]
R489  0  [SM-7351-RES-0402]
R491  4.7K  [SM-7351-RES-0402]
R492  0  [SM-7351-RES-0402]
R493  220  [SM-7351-RES-0402]
R494  10K  [SM-7351-RES-0402]
R495  2.2K  [sm-7351-res-0402]
R496  10K  [SM-7351-RES-0402]
R554  0  [SM-7351-RES-0402]
R555  0  [SM-7351-RES-0402]
R677  0  [SM-7351-RES-0402]
TP18  TP1mm  [tp_smd1mmcircle]
U34  SN74LVC1G00DCK  [U_5_DCK]
U35  SN74LVC1G07  [u_5_dck]
U36  TPD2E001DRLR  [U_5_DRL]
U37  FT2232HL  [LQFP64pin]
U38  93LC56B  [SOIC_8]
U63  SN74AVC4T245  [U_16_PW]
U65  SN74AVC2T244  [son2x1-8-16m]
U75  SN74AVC2T244  [son2x1-8-16m]
Y5  12MHz  [SM_OSC_ABM3]
sheet Pg25: eMMC
C255  10000pF  [CC0402]
C256  10000pF  [CC0402]
C257  10000pF  [CC0402]
C258  10000pF  [CC0402]
C261  10000pF  [CC0402]
C262  10000pF  [CC0402]
C263  10000pF  [CC0402]
C264  10000pF  [CC0402]
C265  1uF  [CC0402]
C350  1uF  [CC0402]
C479  2.2uF  [SM-7351-CAP-0805]
R505  49.9K  [SM-7351-RES-0402]
R506  49.9K  [SM-7351-RES-0402]
R507  49.9K  [SM-7351-RES-0402]
R508  49.9K  [SM-7351-RES-0402]
R509  49.9K  [SM-7351-RES-0402]
R510  49.9K  [SM-7351-RES-0402]
R511  49.9K  [SM-7351-RES-0402]
R512  49.9K  [SM-7351-RES-0402]
R513  49.9K  [SM-7351-RES-0402]
R741  10K  [SM-7351-RES-0402]
U43  MTFC16GAPALBH-IT  [BGA153N50P14x14_1150x1300x140]  (sections A,B)
sheet Pg28: DCAN #1
C249  3.3uF  [CC0603]
C250  3.3uF  [CC0603]
C251  10000pF  [CC0402]
C252  0.1uF  [CC0402]
C253  100pF  [CC0402]
C254  100pF  [CC0402]
J38  HEADER 5  [HEADER_5X1]
R502  33  [SM-7351-RES-0402]
R503  120  [SM-7351-RES-0402]
R504  33  [SM-7351-RES-0402]
U40  R1Z-3.305HP  [smd15x11-6-374m]
U41  ISO1050  [so9x6-8-191m]
U87  TPD1E10B06  [tpd1e10b06-2l]
U88  TPD1E10B06  [tpd1e10b06-2l]
sheet Pg30: RS-485
C449  0.1uF  [CC0402]
J39  HEADER 3  [header_3x1]
R582  0  [SM-7351-RES-0402]
R583  0  [SM-7351-RES-0402]
R584  0  [SM-7351-RES-0402]
R729  100  [SM-7351-RES-0402]
U77  SN65HVD78D  [soic_8]
U82  TPD1E10B06  [tpd1e10b06-2l]
U83  TPD1E10B06  [tpd1e10b06-2l]
sheet Pg35:Hardware
FID1  Fiducial  [Pad]
FID2  Fiducial  [Pad]
FID3  Fiducial  [Pad]
FID4  Fiducial  [Pad]
FID5  Fiducial  [Pad]
FID6  Fiducial  [Pad]
FID7  Fiducial  [Pad]
FID8  Fiducial  [Pad]
FID9  Fiducial  [Pad]
FID10  Fiducial  [Pad]
FID11  Fiducial  [Pad]
FID12  Fiducial  [Pad]
FID13  Fiducial  [Pad]
FID14  Fiducial  [Pad]
FID15  Fiducial  [Pad]
FID16  Fiducial  [Pad]
FID17  Fiducial  [Pad]
FID18  Fiducial  [Pad]
FID19  Fiducial  [Pad]
FID20  Fiducial  [Pad]
FID21  Fiducial  [Pad]
FID22  Fiducial  [Pad]
FID23  Fiducial  [Pad]
FID24  Fiducial  [Pad]
FID25  Fiducial  [Pad]
FID26  Fiducial  [Pad]
FID27  Fiducial  [Pad]
FID28  Fiducial  [Pad]
FID29  Fiducial  [Pad]
FID30  Fiducial  [Pad]
FID31  Fiducial  [Pad]
FID32  Fiducial  [Pad]
FID33  Fiducial  [Pad]
FID34  Fiducial  [Pad]
FID35  Fiducial  [Pad]
FID36  Fiducial  [Pad]
FID37  Fiducial  [Pad]
FID38  Fiducial  [Pad]
LBL1  THT-14-423-10
LBL2  THT-14-423-10
PCB1  PROC053  [DNP]

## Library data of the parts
C29-C32 C34-C43 C48-C51 C55-C63 C65-C79 C81 C216 C219 C225-C230 C232-C236 C238-C240 C242 C251 C255-C258 C261-C264 C315 C408-C410 C420 C424-C429 C443 C444 C448 C480-C482 = CC0402KRX7R7BB103
C33 C52 C64 = CL21A226MOCLRNC
C44-C47 C53 C54 C80 C82 C83 C245 C252 = CC0402JRX7R7BB104
R32-R35 R37-R40 R412 R417 R420 R485 R494 R496 R561 R637 R741 R804 R805 = RMCF0402FT10K0
R41 R42 R44 = 1R_240OhmResistor1_16W0402: Resistor 240 ohm 1/16W 1% 0402; MANUFACTURER: STACKPOLE ELECTRONICS
U5-U7 = MT41K256M16TW-107_AIT_P
C215 C222 = CL21A106KOQNNNG
C217 C231 C237 C241 = 1C_4.7uFCapacitor16V10%0603: Capacitor Ceramic 4.7uF 16V 10% 0603; MANUFACTURER: Taiyo Yuden
C218 = GRT21BR61H475ME13L
C265 C350 C407 C484 = CGB2A1X5R1E105K033BC
FB12 FB19 = 1L_FerBead_0: Ferrite Bead 150 Ohm 800mA; MANUFACTURER: Laird-Signal Integrity Products
J16 = 2C_Conn_FFC_0.5mm_32pos: Connector 0.5mm pitch 32pin FFC top contacts; MANUFACTURER: Omron
J17 = XF2M-0615-1A
L1 = 1L_0.7Asmd: Inductor 4.7uH 30% smt 1.7A; MANUFACTURER: TDK
Q9 = 1Q_MOSFET_NChan_BSS138_0: MANUFACTURER: Diodes Inc.
R410 R411 R416 R418 R451 R473-R478 R480-R483 R486 R487 R489 R492 R554 R555 R558 R559 R565-R567 R582-R586 R605-R628 R634-R636 R677 R682 R683 R792 R795 R796 R906-R911 = 1R_ZeroOhmResistor1_16W0402: Resistor Zero ohm Jumper 0402; MANUFACTURER: PANASONIC
R413 = 1R_10ohm1_16W5%smd0402: Resistor 10ohm 1/16W 5% 0402; MANUFACTURER: STACKPOLE ELECTRONICS
R414 = 1R_47KOhmResistor1_16W0402: Resistor 47Kohm 1/16W 1% 0402; MANUFACTURER: Vishay
R415 = 1R_2OhmResistor1_10W1%0603: Resistor 2.0 ohm 1/10W 1% 0603; MANUFACTURER: Yageo
R630-R633 R687 = 1R_100ohm1_16W1%SMD0402: Resistor 100ohm 1/10W 1% 0402; Cost100: 0.02; MANUFACTURER: PANASONIC; MfrNum: ERJ-2RKF1000X; PartName: 100ohm1/10W1%0402; TIIntPartnumber: 1R0246
TP18 TP24 = 2H_Testpoint_SMD1mmCircle: Testpoint SMD 1mm circle pad; MANUFACTURER: N/A
U32 = TPS61081DRCT: MANUFACTURER: TEXAS INSTRUMENTS
U76 = TPS71712DCKR: MANUFACTURER: TI
U89 = 1A_TC358778XBG: Display Interface Video Parallel to MIPI; MANUFACTURER: Toshiba
J24 = 2C_Conn_HDMI_TypeA: Connector HDMI Type A RA; MANUFACTURER: FCI
L29-L32 = 1M_DLW21SN900HQ2L_0: Common Mode Choke Coil 280mA; MANUFACTURER: Murata
R495 R556 R563 = 1R_2.2KOhmResistor1_16W0402: MANUFACTURER: VishayDale
R484 R491 R560 R562 = 1R_4.7KOhmResistor1_16W0402: Resistor 4.7Kohm 1/16W 5% 0402; MANUFACTURER: STACKPOLE ELECTRONICS
U1 = AM5729BABCXEA
U46 = TPD12S016PWR: MANUFACTURER: TI
C224 C479 = 1C_2.2uF16V10%SMD0805: Capacitor 2.2uF 16V 10% 0805; MANUFACTURER: Kemet
C243 C244 = CL05C180JB5NNNC
D13 = 5988170107F: LED Green SMD 20mA 2V 0805; MANUFACTURER: Dialight
FB9-FB11 = MPZ1608S221ATA00: Ferrite Bead 220 Ohm 2.2A; MANUFACTURER: TDK
J19 = USB: MANUFACTURER: Hirose
R472 = 1R_ZeroOhmResistor1_16W0603: Resistor Zero ohm Jumper 0603; MANUFACTURER: PANASONIC
R479 = 1R_12Kohm1_16W1%SMD0402: Resistor 12Kohm 1/16W 1% 0402; MANUFACTURER: STACKPOLE ELECTRONICS
R493 = 1R_220ohm1_10W1%smd0402: Resistor 220ohm 1/10W 1% 0402; MANUFACTURER: PANASONIC
U34 = SN74LVC1G00DCKR: MANUFACTURER: TEXAS INSTRUMENTS
U35 = SN74LVC1G07DCKRE4: MANUFACTURER: TEXAS INSTRUMENT
U36 = TPD2E001DRLR
U37 = 1A_FT2232_2: USBHS Dual UART/FIFO; MANUFACTURER: FTDI
U38 = 1A_93C56EEPROM2Kbit: E2PROM 2Kbit 3Mhz Memory; MANUFACTURER: Microchip
U63 = 1A_SN74AVC4T245: Bus Transceiver 4bit Voltage Translator; MANUFACTURER: TI
U65 U75 = SN74AVC2T244DQMR: MANUFACTURER: TI
Y5 = 1Y_Crystal12MHzABM3_0: Crystal 12MHz 30ppm load cap 18pF; MANUFACTURER: Abracon
R505-R513 = 1R_49.9KOhmResistor1_16W0402: Resistor 49.9Kohm 1/16W 1% 0402; MANUFACTURER: STACKPOLE ELECTRONICS
U43 = MTFC16GAPALBH-IT
C249 C250 = C1608JB1C335K080AC
C253 C254 = C0402C101J3GACTU
J38 = 2H_Header_5x1: Single Line Header 5pin Tin 0.1in pitch; MANUFACTURER: Sullins
R502 R504 = 1R_33ohmResistor1_16W5%0402: Resistor 33ohm 1/16W 5% 0402; MANUFACTURER: PANASONIC
R503 = 1R_120ohm1_16W1%smd0402: Resistor 120ohm 1/16W 1% 0402; MANUFACTURER: Vishay_Dale
U40 = 1A_IsoReg5V_R1Z-3.305HP: Isolated DC to DC Converter 5V out; MANUFACTURER: Recom
U41 = 1A_ISO1050: Isolated CAN Transceiver; MANUFACTURER: TI
U82 U83 U87 U88 = TPD1E10B06DPYR: TVS DIODE 5.5V 14V 2X1SON; MANUFACTURER: TI
C449 = CGA2B3X7R1H104K050BE
J39 = 2H_Header_3x1: MANUFACTURER: Sullins
R729 = 1R_100ohm1_10W1%SMD0402: Resistor 100ohm 1/10W 1% 0402; MANUFACTURER: PANASONIC; PartName: 100ohm1/10W1%0402
U77 = 1A_SN65HVD78: RS-485 Transceiver with ESD protection; MANUFACTURER: TI
FID1-FID38 = Fiducial
LBL1 LBL2 = THT-14-423-10
PCB1 = 3M_AM572xIDKEVMBarePCB: AM574x Industrial EVM Bare PCB; MANUFACTURER: ANY; PartName: AM572XIndustrialEVMBarePCB; Version: 1.1

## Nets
DGND: C29.2 C30.2 C31.2 C32.2 C33.2 C34.2 C35.2 C36.2 C37.2 C38.2 C39.2 C40.2 C41.2 C42.2 C43.2 C45.2 C46.2 C48.2 C49.2 C50.2 C51.2 C52.2 C53.2 C54.2 C55.2 C56.2 C57.2 C58.2 C59.2 C60.2 C61.2 C62.2 C63.2 C64.2 C65.2 C66.2 C67.2 C68.2 C69.2 C70.2 C71.2 C72.2 C73.2 C74.2 C75.2 C76.2 C77.2 C78.2 C79.2 C81.2 C82.2 C83.2 C215.2 C216.2 C217.2 C218.2 C219.2 C222.2 C224.2 C225.2 C226.2 C227.2 C228.1 C229.2 C230.1 C231.1 C232.2 C233.2 C234.1 C235.2 C236.2 C237.1 C238.2 C239.2 C240.1 C241.2 C242.1 C243.2 C244.2 C245.2 C249.2 C251.2 C253.2 C254.2 C255.2 C256.2 C257.2 C258.2 C261.2 C262.2 C263.2 C264.2 C265.2 C315.2 C350.2 C407.2 C408.2 C409.2 C410.2 C420.2 C424.2 C425.2 C426.2 C427.2 C428.2 C429.2 C443.2 C444.2 C448.2 C449.2 C479.2 C480.2 C481.2 C482.2 C484.2 FB12.2 J16.7 J16.10 J16.13 J16.16 J16.19 J16.22 J16.MNT1 J16.MNT2 J17.6 J17.G1 J17.G2 J19.5(GND) J24.2(DAT2_S) J24.5(DAT1_S) J24.8(DAT0_S) J24.11(CLK_S) J24.17(DDC/CEC_GND) J24.MTG1 J24.MTG2 J24.MTG3 J24.MTG4 J39.3 Q9.S(SOURCE) R32.2 R33.2 R34.2 R35.2 R37.2 R38.2 R39.2 R40.2 R41.1(P1) R42.1(P1) R44.1(P1) R414.1(P1) R415.1 R417.1 R479.2(P2) R484.1(P1) R489.1(P1) R494.1 R561.1 U5.A9(VSS1) U5.B1(VSSQ) U5.B3(VSS2) U5.B9(VSSQ) U5.D1(VSSQ) U5.D8(VSSQ) U5.E1(VSS3) U5.E2(VSSQ) U5.E8(VSSQ) U5.F9(VSSQ) U5.G1(VSSQ) U5.G8(VSS4) U5.G9(VSSQ) U5.J2(VSS5) U5.J8(VSS6) U5.M1(VSS7) U5.M9(VSS8) U5.P1(VSS9) U5.P9(VSS10) U5.T1(VSS11) U5.T9(VSS12) U6.A9(VSS1) U6.B1(VSSQ) U6.B3(VSS2) U6.B9(VSSQ) U6.C7(UDQS) U6.D1(VSSQ) U6.D3(UDM) U6.D8(VSSQ) U6.E1(VSS3) U6.E2(VSSQ) U6.E8(VSSQ) U6.F9(VSSQ) U6.G1(VSSQ) U6.G8(VSS4) U6.G9(VSSQ) U6.J2(VSS5) U6.J8(VSS6) U6.M1(VSS7) U6.M9(VSS8) U6.P1(VSS9) U6.P9(VSS10) U6.T1(VSS11) U6.T9(VSS12) U7.A9(VSS1) U7.B1(VSSQ) U7.B3(VSS2) U7.B9(VSSQ) U7.D1(VSSQ) U7.D8(VSSQ) U7.E1(VSS3) U7.E2(VSSQ) U7.E8(VSSQ) U7.F9(VSSQ) U7.G1(VSSQ) U7.G8(VSS4) U7.G9(VSSQ) U7.J2(VSS5) U7.J8(VSS6) U7.M1(VSS7) U7.M9(VSS8) U7.P1(VSS9) U7.P9(VSS10) U7.T1(VSS11) U7.T9(VSS12) U32.4(GND) U32.8(PGND) U32.PAD(TPAD) U34.3(GND) U35.3(GND) U36.4(GND) U37.1(GND.1) U37.5(GND.2) U37.10(AGND) U37.11(GND.3) U37.13(TEST) U37.15(GND.4) U37.25(GND.5) U37.35(GND.6) U37.47(GND.7) U37.51(GND.8) U38.5(VSS) U38.7(NC1) U40.1(VIN-) U41.4(GND1) U43.A6(VSS1) U43.C4(VSSQ1) U43.E7(VSS2) U43.G5(VSS3) U43.H10(VSS4) U43.J5(VSS5) U43.K8(VSS6) U43.N2(VSSQ2) U43.N5(VSSQ3) U43.P4(VSSQ4) U43.P6(VSSQ5) U46.6(GND) U46.14(GND) U46.19(GND) U63.8(GND) U63.9(GND) U65.5(GND) U75.5(GND) U76.2(GND) U77.5(GND) U82.2 U83.2 U89.A1(VSS) U89.A10(VSS) U89.B7(VSS) U89.D4(VSS) U89.D5(VSS) U89.D6(VSS) U89.D7(VSS) U89.E4(VSS) U89.E5(VSS) U89.E6(VSS) U89.E7(VSS) U89.E9(VSS) U89.F4(VSS) U89.F5(VSS) U89.F6(VSS) U89.F7(VSS) U89.G4(VSS) U89.G5(VSS) U89.G6(VSS) U89.G7(VSS) U89.H2(VSS) U89.H9(VSS) U89.J4(VSS) U89.J5(VSS) U89.J8(CS) U89.K10(VSS) ; also on sheet 9 11 12 13 14 15 16 17 18 19 20 21 22 23 24 25 26 27 28 29 30 31 32 33 34 35
GND_CAN1: C250.2 C252.2 J38.4 U40.4(VOUT-) U40.5(VOUT-) U41.5(GND2) U87.2 U88.2
GNDUSBJ: FB12.1 J19.S1 J19.S2 J19.S3 J19.S4
V1_2D: C480.1 C481.1 C484.1 FB19.1 U76.5(OUT) U89.A7(VDDC) U89.B1(VDDC) U89.K4(VDDC)
V1_2D_EN: R451.1(P1) U76.3(EN)
V1_8D: R451.2(P2) ; also on sheet 19 22 25 28 29 33
V1_8FTDI: C227.1 C232.1 C235.1 C238.1 C241.1 U37.12(VCORE.1) U37.37(VCORE.2) U37.49(VREGOUT) U37.64(VCORE.3)
V3_3D: C219.1 C249.1 C251.1 C255.1 C256.1 C257.1 C258.1 C261.1 C262.1 C263.1 C264.1 C350.1 C408.1 C409.1 C410.1 C420.1 C426.1 C428.1 C444.1 C449.1 C479.1 J17.5 R410.2(P2) R412.2 R417.2 R420.1 R472.2(P2) R505.2(P2) R506.2(P2) R507.2(P2) R508.2(P2) R509.2(P2) R510.2(P2) R511.2(P2) R512.2(P2) R513.2(P2) R556.2(P2) R559.2(P2) R563.2(P2) R637.1 R741.2 R804.2 R805.2 U40.2(VIN+) U41.1(VCC1) U43.C6(VCCQ1) U43.E6(VCC1) U43.F5(VCC2) U43.J10(VCC3) U43.K9(VCC4) U43.M4(VCCQ2) U43.N4(VCCQ3) U43.P3(VCCQ4) U43.P5(VCCQ5) U46.24(VCCA) U63.16(VCCB) U65.8(VCCB) U75.1(VCCA) U75.3(A2) U77.8(VCC) U89.B10(VDDIO) U89.H1(VDDIO) U89.K5(VDDIO) U89.K9(VDDIO) ; also on sheet 9 11 12 13 14 15 16 17 18 19 21 22 23 24 25 26 27 28 29 30 31 32 33 34 35
V3_3FTDI: C224.1 C228.2 C229.1 C230.2 C233.1 C236.1 C239.1 C242.2 C245.1 C425.1 C443.1 C448.1 FB10.2 FB11.2 R472.1(P1) R485.2 R496.2 U34.5(VCC) U35.5(VCC) U37.20(VCCIO.1) U37.31(VCCIO.2) U37.42(VCCIO.3) U37.50(VREGIN) U37.56(VCCIO.4) U38.6(NC2) U38.8(VCC) U63.1(VCCA) U63.2(1DIR) U63.3(2DIR) U65.1(VCCA) U75.8(VCCB)
V3_7LCD: C222.1 C315.1 J16.3 J16.4 J16.5 ; also on sheet 21
V5_0D: C427.1 R560.2(P2) R562.2(P2) U46.11(VCC5V) ; also on sheet 14 16 18 21 34
V5_0HDMICONN: C429.1 J24.18(+5V) U46.13(5V_OUT)
VDDR_VREF: C44.2 C45.1 C46.1 C47.2 C53.1 C54.1 C80.2 C81.1 C82.1 C83.1 U1.Y18(DDR1_VREF) U5.H1(VREFDQ) U5.M8(VREFCA) U6.H1(VREFDQ) U6.M8(VREFCA) U7.H1(VREFDQ) U7.M8(VREFCA) ; also on sheet 9
VDDS_DDR: C29.1 C30.1 C31.1 C32.1 C33.1 C34.1 C35.1 C36.1 C37.1 C38.1 C39.1 C40.1 C41.1 C42.1 C43.1 C44.1 C47.1 C48.1 C49.1 C50.1 C51.1 C52.1 C55.1 C56.1 C57.1 C58.1 C59.1 C60.1 C61.1 C62.1 C63.1 C64.1 C65.1 C66.1 C67.1 C68.1 C69.1 C70.1 C71.1 C72.1 C73.1 C74.1 C75.1 C76.1 C77.1 C78.1 C79.1 C80.1 U5.A1(VDDQ) U5.A8(VDDQ) U5.B2(VDD) U5.C1(VDDQ) U5.C9(VDDQ) U5.D2(VDDQ) U5.D9(VDD) U5.E9(VDDQ) U5.F1(VDDQ) U5.G7(VDD) U5.H2(VDDQ) U5.H9(VDDQ) U5.K2(VDD) U5.K8(VDD) U5.N1(VDD) U5.N9(VDD) U5.R1(VDD) U5.R9(VDD) U6.A1(VDDQ) U6.A8(VDDQ) U6.B2(VDD) U6.B7(\\~{UDQS}) U6.C1(VDDQ) U6.C9(VDDQ) U6.D2(VDDQ) U6.D9(VDD) U6.E9(VDDQ) U6.F1(VDDQ) U6.G7(VDD) U6.H2(VDDQ) U6.H9(VDDQ) U6.K2(VDD) U6.K8(VDD) U6.N1(VDD) U6.N9(VDD) U6.R1(VDD) U6.R9(VDD) U7.A1(VDDQ) U7.A8(VDDQ) U7.B2(VDD) U7.C1(VDDQ) U7.C9(VDDQ) U7.D2(VDDQ) U7.D9(VDD) U7.E9(VDDQ) U7.F1(VDDQ) U7.G7(VDD) U7.H2(VDDQ) U7.H9(VDDQ) U7.K2(VDD) U7.K8(VDD) U7.N1(VDD) U7.N9(VDD) U7.R1(VDD) U7.R9(VDD) ; also on sheet 9 20 21 22
AM57XX_GPIO_RS485: R584.2(P2) U1.AA3(MCASP5_ACLKX/PR2_PRU1_R30_1)
AM57XX_HDMI_CLK+: L29.4 U1.AH16(HDMI1_CLOCKY)
AM57XX_HDMI_CLK-: L29.1 U1.AG16(HDMI1_CLOCKX)
AM57XX_HDMI_TX0+: L30.4 U1.AH17(HDMI1_DATA0Y)
AM57XX_HDMI_TX0-: L30.1 U1.AG17(HDMI1_DATA0X)
AM57XX_HDMI_TX1+: L31.4 U1.AH18(HDMI1_DATA1Y)
AM57XX_HDMI_TX1-: L31.1 U1.AG18(HDMI1_DATA1X)
AM57XX_HDMI_TX2+: L32.4 U1.AH19(HDMI1_DATA2Y)
AM57XX_HDMI_TX2-: L32.1 U1.AG19(HDMI1_DATA2X)
AM57XX_LCD_DE: R634.2(P2) U1.B10(VOUT1_DE)
AM57XX_LCD_HSYNC: R636.2(P2) U1.C11(VOUT1_HSYNC)
AM57XX_LCD_PCLK: R565.2(P2) U1.D11(VOUT1_CLK)
AM57XX_LCD_VSYNC: R635.2(P2) U1.E11(VOUT1_VSYNC)
AM57XX_UART2_RXD: R583.2(P2) U1.D28(UART2_RXD)
AM57XX_UART2_TXD: R582.2(P2) U1.D26(UART2_TXD)
AM57XX_UART3_RXD: R487.1(P1) U1.D27(UART2_CTSn/UART3_RXD)
AM57XX_UART3_TXD: R486.1(P1) U1.C28(UART2_RTSn/UART3_TXD)
AM57XX_VOUT1_D0: R605.2(P2) U1.F11(VOUT1_D0)
AM57XX_VOUT1_D1: R606.2(P2) U1.G10(VOUT1_D1)
AM57XX_VOUT1_D2: R607.2(P2) U1.F10(VOUT1_D2) ; also on sheet 15
AM57XX_VOUT1_D3: R608.2(P2) U1.G11(VOUT1_D3) ; also on sheet 15
AM57XX_VOUT1_D4: R609.2(P2) U1.E9(VOUT1_D4) ; also on sheet 15
AM57XX_VOUT1_D5: R610.2(P2) R910.2(P2) U1.F9(VOUT1_D5) ; also on sheet 15
AM57XX_VOUT1_D6: R612.2(P2) R911.2(P2) U1.F8(VOUT1_D6) ; also on sheet 15
AM57XX_VOUT1_D7: R611.2(P2) R908.2(P2) U1.E7(VOUT1_D7) ; also on sheet 15
AM57XX_VOUT1_D8: R613.2(P2) R909.2(P2) U1.E8(VOUT1_D8)
AM57XX_VOUT1_D9: R614.2(P2) U1.D9(VOUT1)
AM57XX_VOUT1_D10: R616.2(P2) U1.D7(VOUT1_D10) ; also on sheet 15
AM57XX_VOUT1_D11: R615.2(P2) U1.D8(VOUT1_D11) ; also on sheet 15
AM57XX_VOUT1_D12: R617.2(P2) U1.A5(VOUT1_D12) ; also on sheet 15
AM57XX_VOUT1_D13: R619.2(P2) R906.2(P2) U1.C6(VOUT1_D13) ; also on sheet 15
AM57XX_VOUT1_D14: R620.2(P2) R907.2(P2) U1.C8(VOUT1_D14) ; also on sheet 15
AM57XX_VOUT1_D15: R618.2(P2) U1.C7(VOUT1_D15) ; also on sheet 15
AM57XX_VOUT1_D16: R621.2(P2) U1.B7(VOUT1_D16)
AM57XX_VOUT1_D17: R622.2(P2) U1.B8(VOUT1_D17)
AM57XX_VOUT1_D18: R624.2(P2) U1.A7(VOUT1_D18) ; also on sheet 15
AM57XX_VOUT1_D19: R623.2(P2) U1.A8(VOUT1_D19) ; also on sheet 15
AM57XX_VOUT1_D20: R625.2(P2) U1.C9(VOUT1_D20) ; also on sheet 15
AM57XX_VOUT1_D21: R627.2(P2) U1.A9(VOUT1_D21) ; also on sheet 15
AM57XX_VOUT1_D22: R628.2(P2) U1.B9(VOUT1_D22) ; also on sheet 15
AM57XX_VOUT1_D23: R626.2(P2) U1.A10(VOUT1_D23) ; also on sheet 15
AM574X_DCAN1_RX: C253.1 R502.1 U1.G19(DCAN1_RX)
AM574X_DCAN1_TX: R504.1 U1.G20(DCAN1_TX)
AM574X_HDMI_CEC: R683.2(P2) R805.1 U1.B20(SPI1_CS3/HDMI_CEC)
AM574X_HDMI_DDC_SCL: R556.1(P1) R795.2(P2) U1.C25(I2C2_SDA/HDMI1_DDC_SCL) ; also on sheet 25
AM574X_HDMI_DDC_SDA: R563.1(P1) R796.2(P2) U1.F17(I2C2_SCL/HDMI1_DDC_SDA) ; also on sheet 25
AM574X_HDMI_HPD: R682.2(P2) R804.1 U1.B21(SPI1_CS2/HDMI_HPD)
BKLT_EN: Q9.G(GATE) R412.1 R416.1(P1)
BKLT_L: L1.1 U32.1(L)
BKLT_SW: L1.2 U32.10(SW)
CAN1_H: J38.2 R503.2(P2) U41.7(CANH) U88.1
CAN1_L: J38.3 R503.1(P1) U41.6(CANL) U87.1
CAN1_RXDF: R502.2 U41.2(RXD) ; also on sheet 34
CAN1_TXDF: C254.1 R504.2 U41.3(TXD) ; also on sheet 34
DDR_A0: U1.AD20(DDR1_A0) U5.N3(A0) U6.N3(A0) U7.N3(A0) ; also on sheet 9
DDR_A1: U1.AC19(DDR1_A1) U5.P7(A1) U6.P7(A1) U7.P7(A1) ; also on sheet 9
DDR_A2: U1.AC20(DDR1_A2) U5.P3(A2) U6.P3(A2) U7.P3(A2) ; also on sheet 9
DDR_A3: U1.AB19(DDR1_A3) U5.N2(A3) U6.N2(A3) U7.N2(A3) ; also on sheet 9
DDR_A4: U1.AF21(DDR1_A4) U5.P8(A4) U6.P8(A4) U7.P8(A4) ; also on sheet 9
DDR_A5: U1.AH22(DDR1_A5) U5.P2(A5) U6.P2(A5) U7.P2(A5) ; also on sheet 9
DDR_A6: U1.AG23(DDR1_A6) U5.R8(A6) U6.R8(A6) U7.R8(A6) ; also on sheet 9
DDR_A7: U1.AE21(DDR1_A7) U5.R2(A7) U6.R2(A7) U7.R2(A7) ; also on sheet 9
DDR_A8: U1.AF22(DDR1_A8) U5.T8(A8) U6.T8(A8) U7.T8(A8) ; also on sheet 9
DDR_A9: U1.AE22(DDR1_A9) U5.R3(A9) U6.R3(A9) U7.R3(A9) ; also on sheet 9
DDR_A10: U1.AD21(DDR1_A10) U5.L7(A10_AP) U6.L7(A10_AP) U7.L7(A10_AP) ; also on sheet 9
DDR_A11: U1.AD22(DDR1_A11) U5.R7(A11) U6.R7(A11) U7.R7(A11) ; also on sheet 9
DDR_A12: U1.AC21(DDR1_A12) U5.N7(A12~{/BC}) U6.N7(A12~{/BC}) U7.N7(A12~{/BC}) ; also on sheet 9
DDR_A13: U1.AF18(DDR1_A13) U5.T3(A13) U6.T3(A13) U7.T3(A13) ; also on sheet 9
DDR_A14: U1.AE17(DDR1_A14) U5.T7(A14) U6.T7(A14) U7.T7(A14) ; also on sheet 9
DDR_A15: U1.AD18(DDR1_A15) U5.M7(NC5) U6.M7(NC5) U7.M7(NC5) ; also on sheet 9
DDR_BA0: U1.AF17(DDR1_BA0) U5.M2(BA0) U6.M2(BA0) U7.M2(BA0) ; also on sheet 9
DDR_BA1: U1.AE18(DDR1_BA1) U5.N8(BA1) U6.N8(BA1) U7.N8(BA1) ; also on sheet 9
DDR_BA2: U1.AB18(DDR1_BA2) U5.M3(BA2) U6.M3(BA2) U7.M3(BA2) ; also on sheet 9
DDR_CASn: U1.AC18(DDR1_CASn) U5.K3(\\~{CAS}) U6.K3(\\~{CAS}) U7.K3(\\~{CAS}) ; also on sheet 9
DDR_CKE: U1.AG22(DDR1_CKE) U5.K9(CKE) U6.K9(CKE) U7.K9(CKE) ; also on sheet 9
DDR_CLK: U1.AG24(DDR1_CK) U5.J7(CK) U6.J7(CK) U7.J7(CK) ; also on sheet 9
DDR_CLKn: U1.AH24(DDR1_CKn) U5.K7(\\~{CK}) U6.K7(\\~{CK}) U7.K7(\\~{CK}) ; also on sheet 9
DDR_CS0n: U1.AH23(DDR1_CSN0) U5.L2(\\~{CS}) U6.L2(\\~{CS}) U7.L2(\\~{CS}) ; also on sheet 9
DDR_D0: U1.AF25(DDR1_D0) U5.E3(DQ0)
DDR_D1: U1.AF26(DDR1_D1) U5.F7(DQ1)
DDR_D2: U1.AG26(DDR1_D2) U5.F8(DQ3)
DDR_D3: U1.AH26(DDR1_D3) U5.H8(DQ5)
DDR_D4: U1.AF24(DDR1_D4) U5.F2(DQ2)
DDR_D5: U1.AE24(DDR1_D5) U5.G2(DQ6)
DDR_D6: U1.AF23(DDR1_D6) U5.H3(DQ4)
DDR_D7: U1.AE23(DDR1_D7) U5.H7(DQ7)
DDR_D8: U1.AC23(DDR1_D8) U5.D7(DQ8)
DDR_D9: U1.AF27(DDR1_D9) U5.C3(DQ9)
DDR_D10: U1.AG27(DDR1_D10) U5.A3(DQ15)
DDR_D11: U1.AF28(DDR1_D11) U5.A7(DQ12)
DDR_D12: U1.AE26(DDR1_D12) U5.A2(DQ13)
DDR_D13: U1.AC25(DDR1_D13) U5.C8(DQ10)
DDR_D14: U1.AC24(DDR1_D14) U5.B8(DQ14)
DDR_D15: U1.AD25(DDR1_D15) U5.C2(DQ11)
DDR_D16: U1.V20(DDR1_D16) U7.E3(DQ0)
DDR_D17: U1.W20(DDR1_D17) U7.H8(DQ5)
DDR_D18: U1.AB28(DDR1_D18) U7.H3(DQ4)
DDR_D19: U1.AC28(DDR1_D19) U7.G2(DQ6)
DDR_D20: U1.AC27(DDR1_D20) U7.F2(DQ2)
DDR_D21: U1.Y19(DDR1_D21) U7.F7(DQ1)
DDR_D22: U1.AB27(DDR1_D22) U7.H7(DQ7)
DDR_D23: U1.Y20(DDR1_D23) U7.F8(DQ3)
DDR_D24: U1.AA23(DDR1_D24) U7.D7(DQ8)
DDR_D25: U1.Y22(DDR1_D25) U7.C3(DQ9)
DDR_D26: U1.Y23(DDR1_D26) U7.B8(DQ14)
DDR_D27: U1.AA24(DDR1_D27) U7.A2(DQ13)
DDR_D28: U1.Y24(DDR1_D28) U7.C2(DQ11)
DDR_D29: U1.AA26(DDR1_D29) U7.A7(DQ12)
DDR_D30: U1.AA25(DDR1_D30) U7.C8(DQ10)
DDR_D31: U1.AA28(DDR1_D31) U7.A3(DQ15)
DDR_DQM0: U1.AD23(DDR1_DQM0) U5.E7(LDM)
DDR_DQM1: U1.AB23(DDR1_DQM1) U5.D3(UDM)
DDR_DQM2: U1.AC26(DDR1_DQM2) U7.E7(LDM)
DDR_DQM3: U1.AA27(DDR1_DQM3) U7.D3(UDM)
DDR_DQS0: U1.AH25(DDR1_DQS0) U5.F3(LDQS)
DDR_DQS1: U1.AE27(DDR1_DQS1) U5.C7(UDQS)
DDR_DQS2: U1.AD27(DDR1_DQS2) U7.F3(LDQS)
DDR_DQS3: U1.Y28(DDR1_DQS3) U7.C7(UDQS)
DDR_DQSn0: U1.AG25(DDR1_DQS0n) U5.G3(\\~{LDQS})
DDR_DQSn1: U1.AE28(DDR1_DQS1n) U5.B7(\\~{UDQS})
DDR_DQSn2: U1.AD28(DDR1_DQS2n) U7.G3(\\~{LDQS})
DDR_DQSn3: U1.Y27(DDR1_DQS3n) U7.B7(\\~{UDQS})
DDR_ODT: U1.AE20(DDR1_ODT0) U5.K1(ODT) U6.K1(ODT) U7.K1(ODT) ; also on sheet 9
DDR_RASn: U1.AF20(DDR1_RASn) U5.J3(\\~{RAS}) U6.J3(\\~{RAS}) U7.J3(\\~{RAS}) ; also on sheet 9
DDR_RESETn: U1.AG21(DDR1_RST) U5.T2(\\~{RESET}) U6.T2(\\~{RESET}) U7.T2(\\~{RESET}) ; also on sheet 9
DDR_WEn: U1.AH21(DDR1_WEn) U5.L3(\\~{WE}) U6.L3(\\~{WE}) U7.L3(\\~{WE}) ; also on sheet 9
DDRECC_D0: U1.W22(DDR1_ECC_D0) U6.E3(DQ0)
DDRECC_D1: U1.V23(DDR1_ECC_D1) U6.F7(DQ1)
DDRECC_D2: U1.W19(DDR1_ECC_D2) U6.H8(DQ5)
DDRECC_D3: U1.W23(DDR1_ECC_D3) U6.F8(DQ3)
DDRECC_D4: U1.Y25(DDR1_ECC_D4) U6.F2(DQ2)
DDRECC_D5: U1.V24(DDR1_ECC_D5) U6.H7(DQ7)
DDRECC_D6: U1.V25(DDR1_ECC_D6) U6.H3(DQ4)
DDRECC_D7: U1.Y26(DDR1_ECC_D7) U6.G2(DQ6)
DDRECC_DQM: U1.V26(DDR1_ECC_DQM) U6.E7(LDM)
DDRECC_DQS: U1.V27(DDR1_ECC_DQS) U6.F3(LDQS)
DDRECC_DQSn: U1.V28(DDR1_ECC_DQSn) U6.G3(\\~{LDQS})
EECS: U37.63(EECS) U38.1(CS)
EEDATA: R495.1(P1) U37.61(EEDATA) U38.3(DI)
EESK: U37.62(EESK) U38.2(CLK)
eMMC_RSTn: R741.1 U43.K5(RST_N) ; also on sheet 34
EMU_USB_DM: J19.2(DM) U36.5(IO2) U37.7(DM)
EMU_USB_DP: J19.3(DP) U36.3(IO1) U37.8(DP)
F_ADBUS0: R474.2(P2) U37.16(ADBUS0)
F_ADBUS1: R475.2(P2) U37.17(ADBUS1)
F_ADBUS2: R480.2(P2) U37.18(ADBUS2)
F_ADBUS3: R481.2(P2) U37.19(ADBUS3)
F_ADBUS4: R476.2(P2) U37.21(ADBUS4)
F_ADBUS5: R478.2(P2) U37.26(ACBUS0)
F_ADBUS6: R477.2(P2) U37.23(ADBUS6)
F_ADBUS7: R483.2(P2) U37.30(ACBUS4)
FT_SRESET: R478.1(P1) R484.2(P2) U34.1(A)
FT_SRESETB: R473.2(P2) U35.4(Y)
FT_SRESETn: U34.4(Y) U35.2(A)
FT_VBUS: R492.1(P1) U34.2(B)
FTDI_REF: R479.1(P1) U37.6(REF)
FTDI_VPHY: C231.2 C234.2 FB10.1 U37.4(VPHY)
FTDI_VPLL: C237.2 C240.2 FB11.1 U37.9(VPLL)
GPIO_TOUCH_RESETn: R792.2(P2) ; also on sheet 34
HDMI_CEC: R683.1(P1) U46.1(CEC_A)
HDMI_CLK+: J24.10(CLK+) L29.3 U46.16(TMDS_CK+)
HDMI_CLK-: J24.12(CLK-) L29.2 U46.15(TMDS_CK-)
HDMI_CT_HPD: R558.2(P2) R559.1(P1) U46.12(CT_HPD)
HDMI_DDC_SCL: R795.1(P1) U46.2(SCL_A)
HDMI_DDC_SDA: R796.1(P1) U46.3(SDA_A)
HDMI_HPLG: R682.1(P1) U46.4(HPD_A)
HDMI_LSOE: R558.1(P1) U46.5(LS_OE)
HDMI_TX0+: J24.7(DAT0+) L30.3 U46.18(TMDS_D0+)
HDMI_TX0-: J24.9(DAT0-) L30.2 U46.17(TMDS_D0-)
HDMI_TX1+: J24.4(DAT1+) L31.3 U46.21(TMDS_D1+)
HDMI_TX1-: J24.6(DAT1-) L31.2 U46.20(TMDS_D1-)
HDMI_TX2+: J24.1(DAT2+) L32.3 U46.23(TMDS_D2+)
HDMI_TX2-: J24.3(DAT2-) L32.2 U46.22(TMDS_D2-)
HDMICONN_CEC: J24.13(CEC) U46.7(CEC_B)
HDMICONN_HPLG: J24.19(HPLG) R561.2 U46.10(HPD_B)
HDMICONN_I2CSCL: J24.15(SCL) R560.1(P1) U46.8(SCL_B)
HDMICONN_I2CSDA: J24.16(SDA) R562.1(P1) U46.9(SDA_B)
IND_I2C_SCL: J17.2 R567.2(P2) ; also on sheet 13 15 18 19 23 28 34
IND_I2C_SDA: J17.1 R585.2(P2) ; also on sheet 13 15 18 19 23 28 34
JTAG_EMU0: R554.1(P1) ; also on sheet 15
JTAG_EMU1: R555.1(P1) ; also on sheet 15
JTAG_TCK: U63.13(1B1) ; also on sheet 15
JTAG_TDI: U63.12(1B2) ; also on sheet 15
JTAG_TDO: U75.2(A1) ; also on sheet 15
JTAG_TMS: U63.11(2B1) ; also on sheet 15
JTAG_TRSTn: U63.10(2B2) ; also on sheet 15
JTAGPOD_PRES: R677.1(P1) ; also on sheet 15
LCD_B0: R605.1(P1) U89.J3(PD0)
LCD_B1: R606.1(P1) U89.K3(PD1)
LCD_B2: R607.1(P1) U89.J2(PD2)
LCD_B3: R608.1(P1) U89.K2(PD3)
LCD_B4: R609.1(P1) U89.J1(PD4)
LCD_B5: R610.1(P1) U89.K1(PD5)
LCD_B6: R612.1(P1) U89.G2(PD6)
LCD_B7: R611.1(P1) U89.G1(PD7)
LCD_BACKLIGHT: R416.2(P2) U1.D1(VIN2A_D2/eCAP1_IN_PWM1)
LCD_CLKN: J16.20 R632.1(P1) U89.F10(MIPI_CN)
LCD_CLKP: J16.21 R632.2(P2) U89.F9(MIPI_CP)
LCD_DEN: R634.1(P1) U89.J7(DE)
LCD_G0: R613.1(P1) U89.F2(PD8)
LCD_G1: R614.1(P1) U89.F1(PD9)
LCD_G2: R616.1(P1) U89.E2(PD10)
LCD_G3: R615.1(P1) U89.E1(PD11)
LCD_G4: R617.1(P1) U89.D2(PD12)
LCD_G5: R619.1(P1) U89.D1(PD13)
LCD_G6: R620.1(P1) U89.C2(PD14)
LCD_G7: R618.1(P1) U89.C1(PD15)
LCD_HS: R636.1(P1) U89.K8(HSYNC)
LCD_MIPI0N: J16.17 R630.2(P2) U89.J10(MIPI_D0N)
LCD_MIPI0P: J16.18 R630.1(P1) U89.J9(MIPI_D0P)
LCD_MIPI1N: J16.14 R631.2(P2) U89.G10(MIPI_D1N)
LCD_MIPI1P: J16.15 R631.1(P1) U89.G9(MIPI_D1P)
LCD_MIPI2N: J16.11 R633.1(P1) U89.D10(MIPI_D2N)
LCD_MIPI2P: J16.12 R633.2(P2) U89.D9(MIPI_D2P)
LCD_MIPI3N: J16.8 R687.1(P1) U89.C10(MIPI_D3N)
LCD_MIPI3P: J16.9 R687.2(P2) U89.C9(MIPI_D3P)
LCD_PCLK: R565.1(P1) U89.J6(PCLK)
LCD_R0: R621.1(P1) U89.B2(PD16)
LCD_R1: R622.1(P1) U89.A2(PD17)
LCD_R2: R624.1(P1) U89.B3(PD18)
LCD_R3: R623.1(P1) U89.A3(PD19)
LCD_R4: R625.1(P1) U89.B4(PD20)
LCD_R5: R627.1(P1) U89.A4(PD21)
LCD_R6: R628.1(P1) U89.B5(PD22)
LCD_R7: R626.1(P1) U89.A5(PD23)
LCD_VS: R635.1(P1) U89.K7(VSYNC)
MMC2_CLK: U1.J7(GPMC_A23/MMC2_CLK) U43.M6(CLK)
MMC2_CMD: R513.1(P1) U1.H6(GPMC_CS1/MMC2_CMD) U43.M5(CMD)
MMC2_DAT0: R505.1(P1) U1.J4(GPMC_A24/MMC2_DAT0) U43.A3(DAT0)
MMC2_DAT1: R506.1(P1) U1.J6(GPMC_A25/MMC2_DAT1) U43.A4(DAT1)
MMC2_DAT2: R507.1(P1) U1.H4(GPMC_A26/MMC2_DAT2) U43.A5(DAT2)
MMC2_DAT3: R508.1(P1) U1.H5(GPMC_A27/MMC2_DAT3) U43.B2(DAT3)
MMC2_DAT4: R509.1(P1) U1.K7(GPMC_A19/MMC2_DAT4) U43.B3(DAT4)
MMC2_DAT5: R510.1(P1) U1.M7(GPMC_A20/MMC2_DAT5) U43.B4(DAT5)
MMC2_DAT6: R511.1(P1) U1.J5(GPMC_A21/MMC2_DAT6) U43.B5(DAT6)
MMC2_DAT7: R512.1(P1) U1.K6(GPMC_A22/MMC2_DAT7) U43.B6(DAT7)
PR2_EDC_LATCH0: R910.1(P1) ; also on sheet 34
PR2_EDC_LATCH1: R911.1(P1) ; also on sheet 34
PR2_EDC_SYNC0: R908.1(P1) ; also on sheet 11 34
PR2_EDC_SYNC1: R909.1(P1) ; also on sheet 34
PR2_UART0_RXD: R906.1(P1) ; also on sheet 11 34
PR2_UART0_TXD: R907.1(P1) ; also on sheet 11 34
RS485_A: J39.1 R729.2(P2) U77.6(A) U82.1
RS485_B: J39.2 R729.1(P1) U77.7(B) U83.1
SRCCLK: R586.2(P2) ; also on sheet 13
SYS_RESETn: R566.2(P2) ; also on sheet 30 31 34
SYS_WARMRESETn: R473.1(P1) ; also on sheet 15 31
TOUCH_INT: R418.2(P2) ; also on sheet 34
TSC_INT: J17.4 R418.1(P1)
TSC_RESETn: J17.3 R420.2 R792.1(P1)
UARTx_RXD: R487.2(P2) U37.38(BDBUS0)
UARTx_TXD: R486.2(P2) U37.39(BDBUS1)
USBJTAG_ENn: R677.2(P2) U63.14(2~{OE}) U63.15(1~{OE}) U65.4(~{OE}) U75.4(~{OE})
VCAN1: C250.1 C252.1 J38.1 U40.7(VOUT+) U41.8(VCC2)
VLED+: C215.1 C216.1 C218.1 J16.29 J16.30 U32.9(OUT)
VLED-: J16.23 J16.24 J16.25 J16.26 J16.27 J16.28 R415.2 U32.5(FB)
VMAIN: C217.1 C407.1 R411.2(P2) U32.2(VIN) U76.1(IN) ; also on sheet 11 13 19 21 34
VUSB_FTDI: C226.1 D13.2(Anode) FB9.2 R491.2(P2)
VUSB_JTAG: C225.1 FB9.1 J19.1(VBUS) U36.1(VCC)
XTIN: C243.1 U37.2(XTIN) Y5.1
XTOUT: C244.1 U37.3(XTOUT) Y5.2
N12957779: R482.2(P2) U37.28(ACBUS2)
N12957783: R482.1(P1) U75.6(B2)
N12957791: R489.2(P2) U37.32(ACBUS5)
N12957851: R491.1(P1) R492.2(P2) R494.2 U37.59(BCBUS7)
N12958009: R485.1 U37.14(RESET#)
N12958129: D13.1(Cathode) R493.2
N12958219: R495.2(P2) R496.1 U38.4(DO)
N12958339: TP18.1 U37.36(SUSPEND#)
N12958347: R493.1 U37.60(PWREN#)
N12958879: R474.1(P1) U63.4(1A1)
N12958935: R476.1(P1) U63.7(2A2)
N12958939: R481.1(P1) U63.6(2A1)
N12958943: R480.1(P1) U75.7(B1)
N12958955: R475.1(P1) U63.5(1A2)
N17732522: R410.1(P1) U32.6(EN)
N17732526: R413.2(P2) R414.2(P2) U32.3(SS)
N17732536: Q9.D(DRAIN) R413.1(P1)
N17732560: R411.1(P1) U32.7(FSW)
N19120663: R41.2(P2) U5.L8(ZQ)
N19139994: R32.1 U6.D7(DQ8)
N19139997: R33.1 U6.C3(DQ9)
N19140025: R34.1 U6.C8(DQ10)
N19140027: R35.1 U6.C2(DQ11)
N19140065: R37.1 U6.A7(DQ12)
N19140067: R38.1 U6.A2(DQ13)
N19140105: R39.1 U6.B8(DQ14)
N19140107: R40.1 U6.A3(DQ15)
N19388440: R566.1(P1) U89.B9(RESXn)
N19438966: R582.1(P1) U1.AB9(MCASP5_FSX/PR2_PRU1_R31_2) U77.4(D)
N19438972: R583.1(P1) U77.1(R)
N19438984: R584.1(P1) U77.2(~{RE}) U77.3(DE)
N20144297: R637.2 U89.A9(MSEL)
N20706534: R554.2(P2) U65.7(B1)
N20706536: R555.2(P2) U65.6(B2)
N20706626: R477.1(P1) U65.2(A1)
N20706635: R483.1(P1) U65.3(A2)
N21099488: C265.1 U43.C2(VDDIM)
N21306186: TP24.1 U89.B6(GPIO1)
N21306311: R567.1(P1) U89.A8(I2C_SCL)
N21306314: R585.1(P1) U89.B8(I2C_SDA)
N21306347: C424.1 C482.1 FB19.2 U89.E10(VDD_MIPI) U89.H10(VDD_MIPI)
N21307911: R586.1(P1) U89.K6(REFCLK)
N24911250: R44.2(P2) U7.L8(ZQ)
N24924145: R42.2(P2) U6.L8(ZQ)

Not connected (* = marked no-connect by the designer): J16 1* 2* 6* 31* 32*; J19 4(ID)*; J24 14(NC)*; J38 5*; U5 J1(NC1)* J9(NC2)* L1(NC3)* L9(NC4)*; U6 J1(NC1)* J9(NC2)* L1(NC3)* L9(NC4)*; U7 J1(NC1)* J9(NC2)* L1(NC3)* L9(NC4)*; U35 1(NC)*; U36 2(NC)*; U37 22(ADBUS5)* 24(ADBUS7)* 27(ACBUS1)* 29(ACBUS3)* 33(ACBUS6)* 34(ACBUS7)* 40(BDBUS2)* 41(BDBUS3)* 43(BDBUS4)* 44(BDBUS5)* 45(BDBUS6)* 46(BDBUS7)* 48(BCBUS0)* 52(BCBUS1)* 53(BCBUS2)* 54(BCBUS3)* 55(BCBUS4)* 57(BCBUS5)* 58(BCBUS6)*; U40 10(NC)*; U43 A1(NC_1)* A2(NC_2)* A7(RFU1)* A8(NC_3)* A9(NC_4)* A10(NC_5)* A11(NC_6)* A12(NC_7)* A13(NC_8)* A14(NC_9)* B1(NC_10)* B7(NC_11)* B8(NC_12)* B9(NC_13)* B10(NC_14)* B11(NC_15)* B12(NC_16)* B13(NC_17)* B14(NC_18)* C1(NC_19)* C3(NC_20)* C5(NC_21)* C7(NC_22)* C8(NC_23)* C9(NC_24)* C10(NC_25)* C11(NC_26)* C12(NC_27)* C13(NC_28)* C14(NC_29)* D1(NC_30)* D2(NC_31)* D3(NC_32)* D4(NC_33)* D12(NC_34)* D13(NC_35)* D14(NC_36)* E1(NC_37)* E2(NC_38)* E3(NC_39)* E5(RFU2)* E8(VSF1)* E9(VSF2)* E10(VSF3)* E12(NC_40)* E13(NC_41)* E14(NC_42)* F1(NC_43)* F2(NC_44)* F3(NC_45)* F10(VSF4)* F12(NC_46)* F13(NC_47)* F14(NC_48)* G1(NC_49)* G2(NC_50)* G3(NC_51)* G10(VSF5)* G12(NC_52)* G13(NC_53)* G14(NC_54)* H1(NC_55)* H2(NC_56)* H3(NC_57)* H5(DS)* H12(NC_58)* H13(NC_59)* H14(NC_60)* J1(NC_61)* J2(NC_62)* J3(NC_63)* J12(NC_64)* J13(NC_65)* J14(NC_66)* K1(NC_67)* K2(NC_68)* K3(NC_69)* K6(RFU8)* K7(RFU9)* K10(VSF6)* K12(NC_70)* K13(NC_71)* K14(NC_72)* L1(NC_73)* L2(NC_74)* L3(NC_75)* L12(NC_76)* L13(NC_77)* L14(NC_78)* M1(NC_79)* M2(NC_80)* M3(NC_81)* M7(NC_82)* M8(NC_83)* M9(NC_84)* M10(NC_85)* M11(NC_86)* M12(NC_87)* M13(NC_88)* M14(NC_89)* N1(NC_90)* N3(NC_91)* N6(NC_92)* N7(NC_93)* N8(NC_94)* N9(NC_95)* N10(NC_96)* N11(NC_97)* N12(NC_98)* N13(NC_99)* N14(NC_100)* P1(NC_101)* P2(NC_102)* P7(NC_103)* P8(NC_104)* P9(NC_105)* P10(VSF7)* P11(NC_106)* P12(NC_107)* P13(NC_108)* P14(NC_109)*; U76 4(NR)*; U89 A6(GPIO2)*

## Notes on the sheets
sheet 1
- Note that ECC use is
  highly constrained -
  please refer to the
  AM574x Errata document
  for more information
sheet 2
- USB JTAG
sheet 5
- LCD Module
- BackLight Power
sheet 6
- eMMC Memory
sheet 7
- Assembly Notes:
  1.  These assemblies are ESD sensitive.
  ESD precautians shall be observed.
  2.  These assemblies must be clean and
  free from flux and all contaminants.  Use
  of 'no clean flux' is not acceptable.
  3.  These assemblies must comply with
  workmanship standard IPC-A-610 Class 2,
  unless otherwise specified.
  4.  Each finished board will receive a
  serial number  sticker during final
  testing.
  5.  Each finished board will receive a
  MAC Address  sticker during final
  testing.
  6.  Install header shunt M1 (on J49) and
  M2 (on J50) during final testing.
- PCB LOGO:
  Texas Instruments
- PCB LOGO:
  WEEE and CE
- U1 Fiducials
- U3 Fiducials
- U37 Fiducials
- U45 Fiducials
- PCB LOGO:
  FCC disclaimer
- U21 Fiducials
- U24 Fiducials
- U9 Fiducials
- U13 Fiducials
- U15 Fiducials
- U17 Fiducials
- U5 Fiducials
- U6 Fiducials
- PCB LOGO:
  Caution Hot Surface
- U89 Fiducials
- U90 Fiducials
- U91 Fiducials
- PCB Top Fiducials
- PCB Bottom Fiducials
- Install label in silkscreened box after final wash.
- Text shall be 8 pt. Text shall be per the label table in the PDF schematics
- Variant / Label Table
- Variant
- Label Text
- 001
- TMDSIDK574
- 002
- TMDSIDK574H
- 003
- TMDSIDK572
